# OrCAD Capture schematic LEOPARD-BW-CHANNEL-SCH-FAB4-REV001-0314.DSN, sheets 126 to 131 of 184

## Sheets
126 041_CPU2 - DDR4 (CHANNEL F): size A3; title: CPU2 - DDR4 (CHANNEL F)
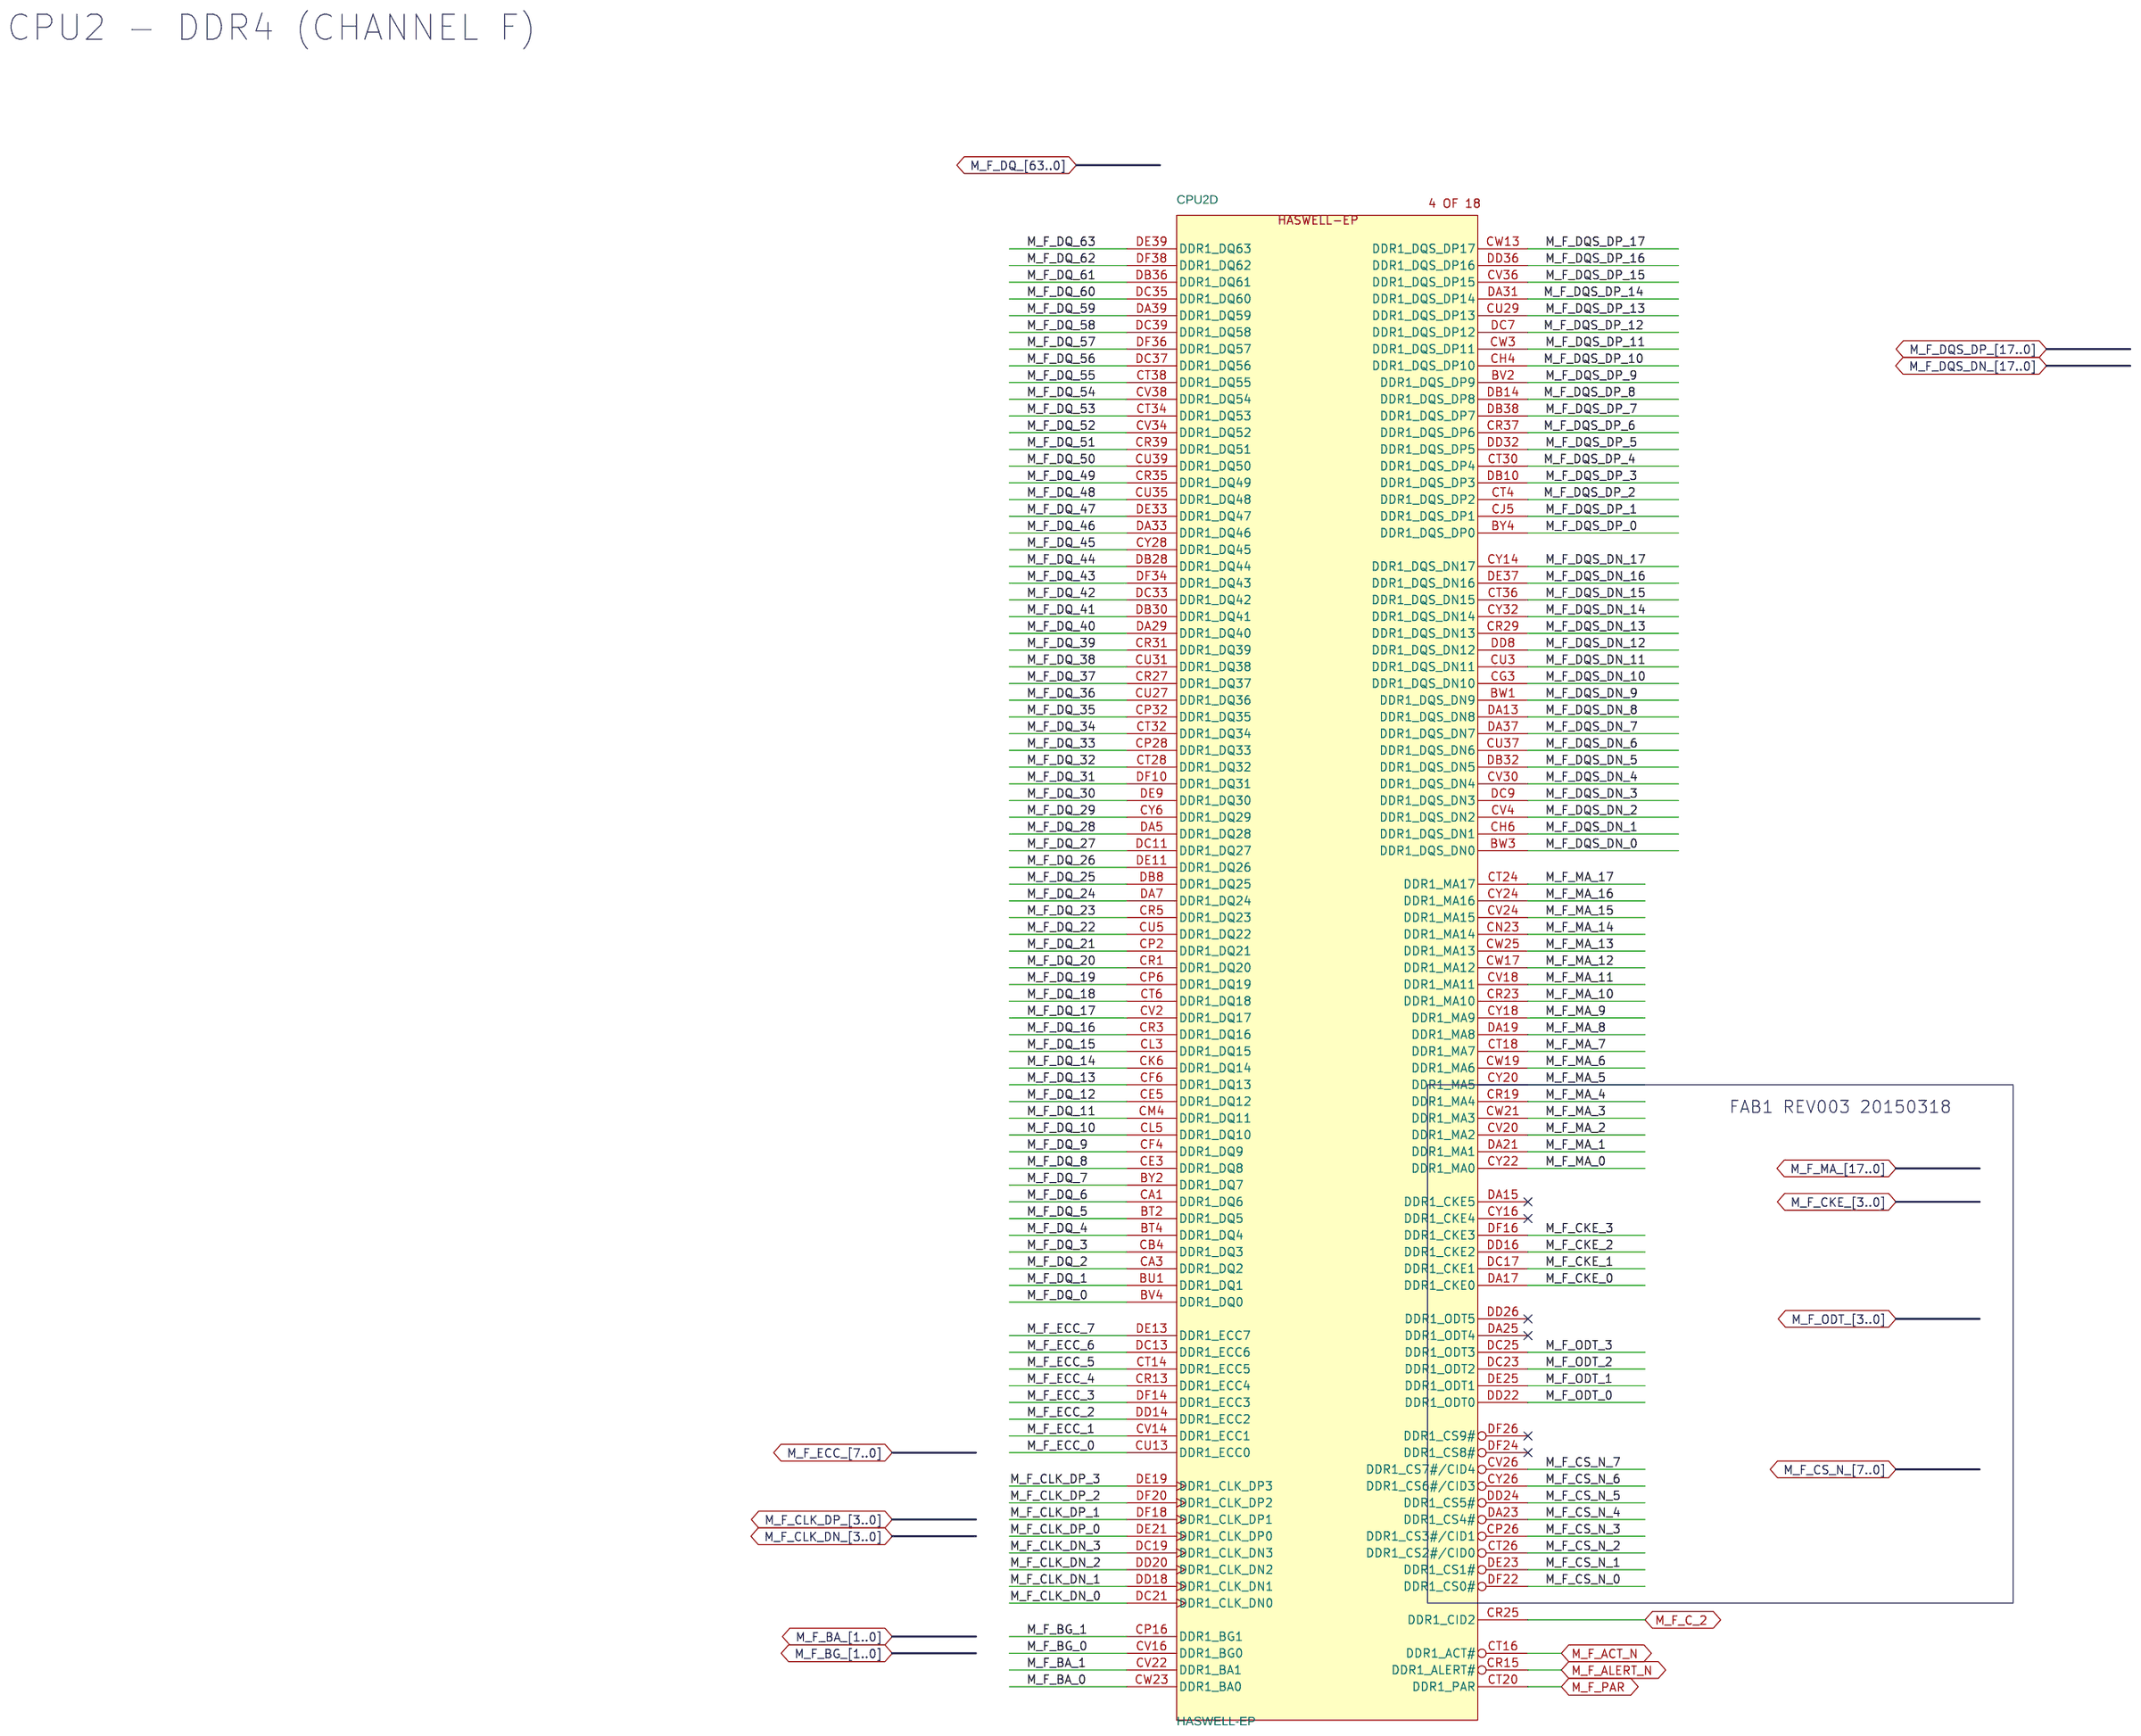
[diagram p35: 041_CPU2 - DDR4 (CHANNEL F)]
127 040_CPU2 - DDR4 (CHANNEL E): size A3; title: CPU2 - DDR4 (CHANNEL E)
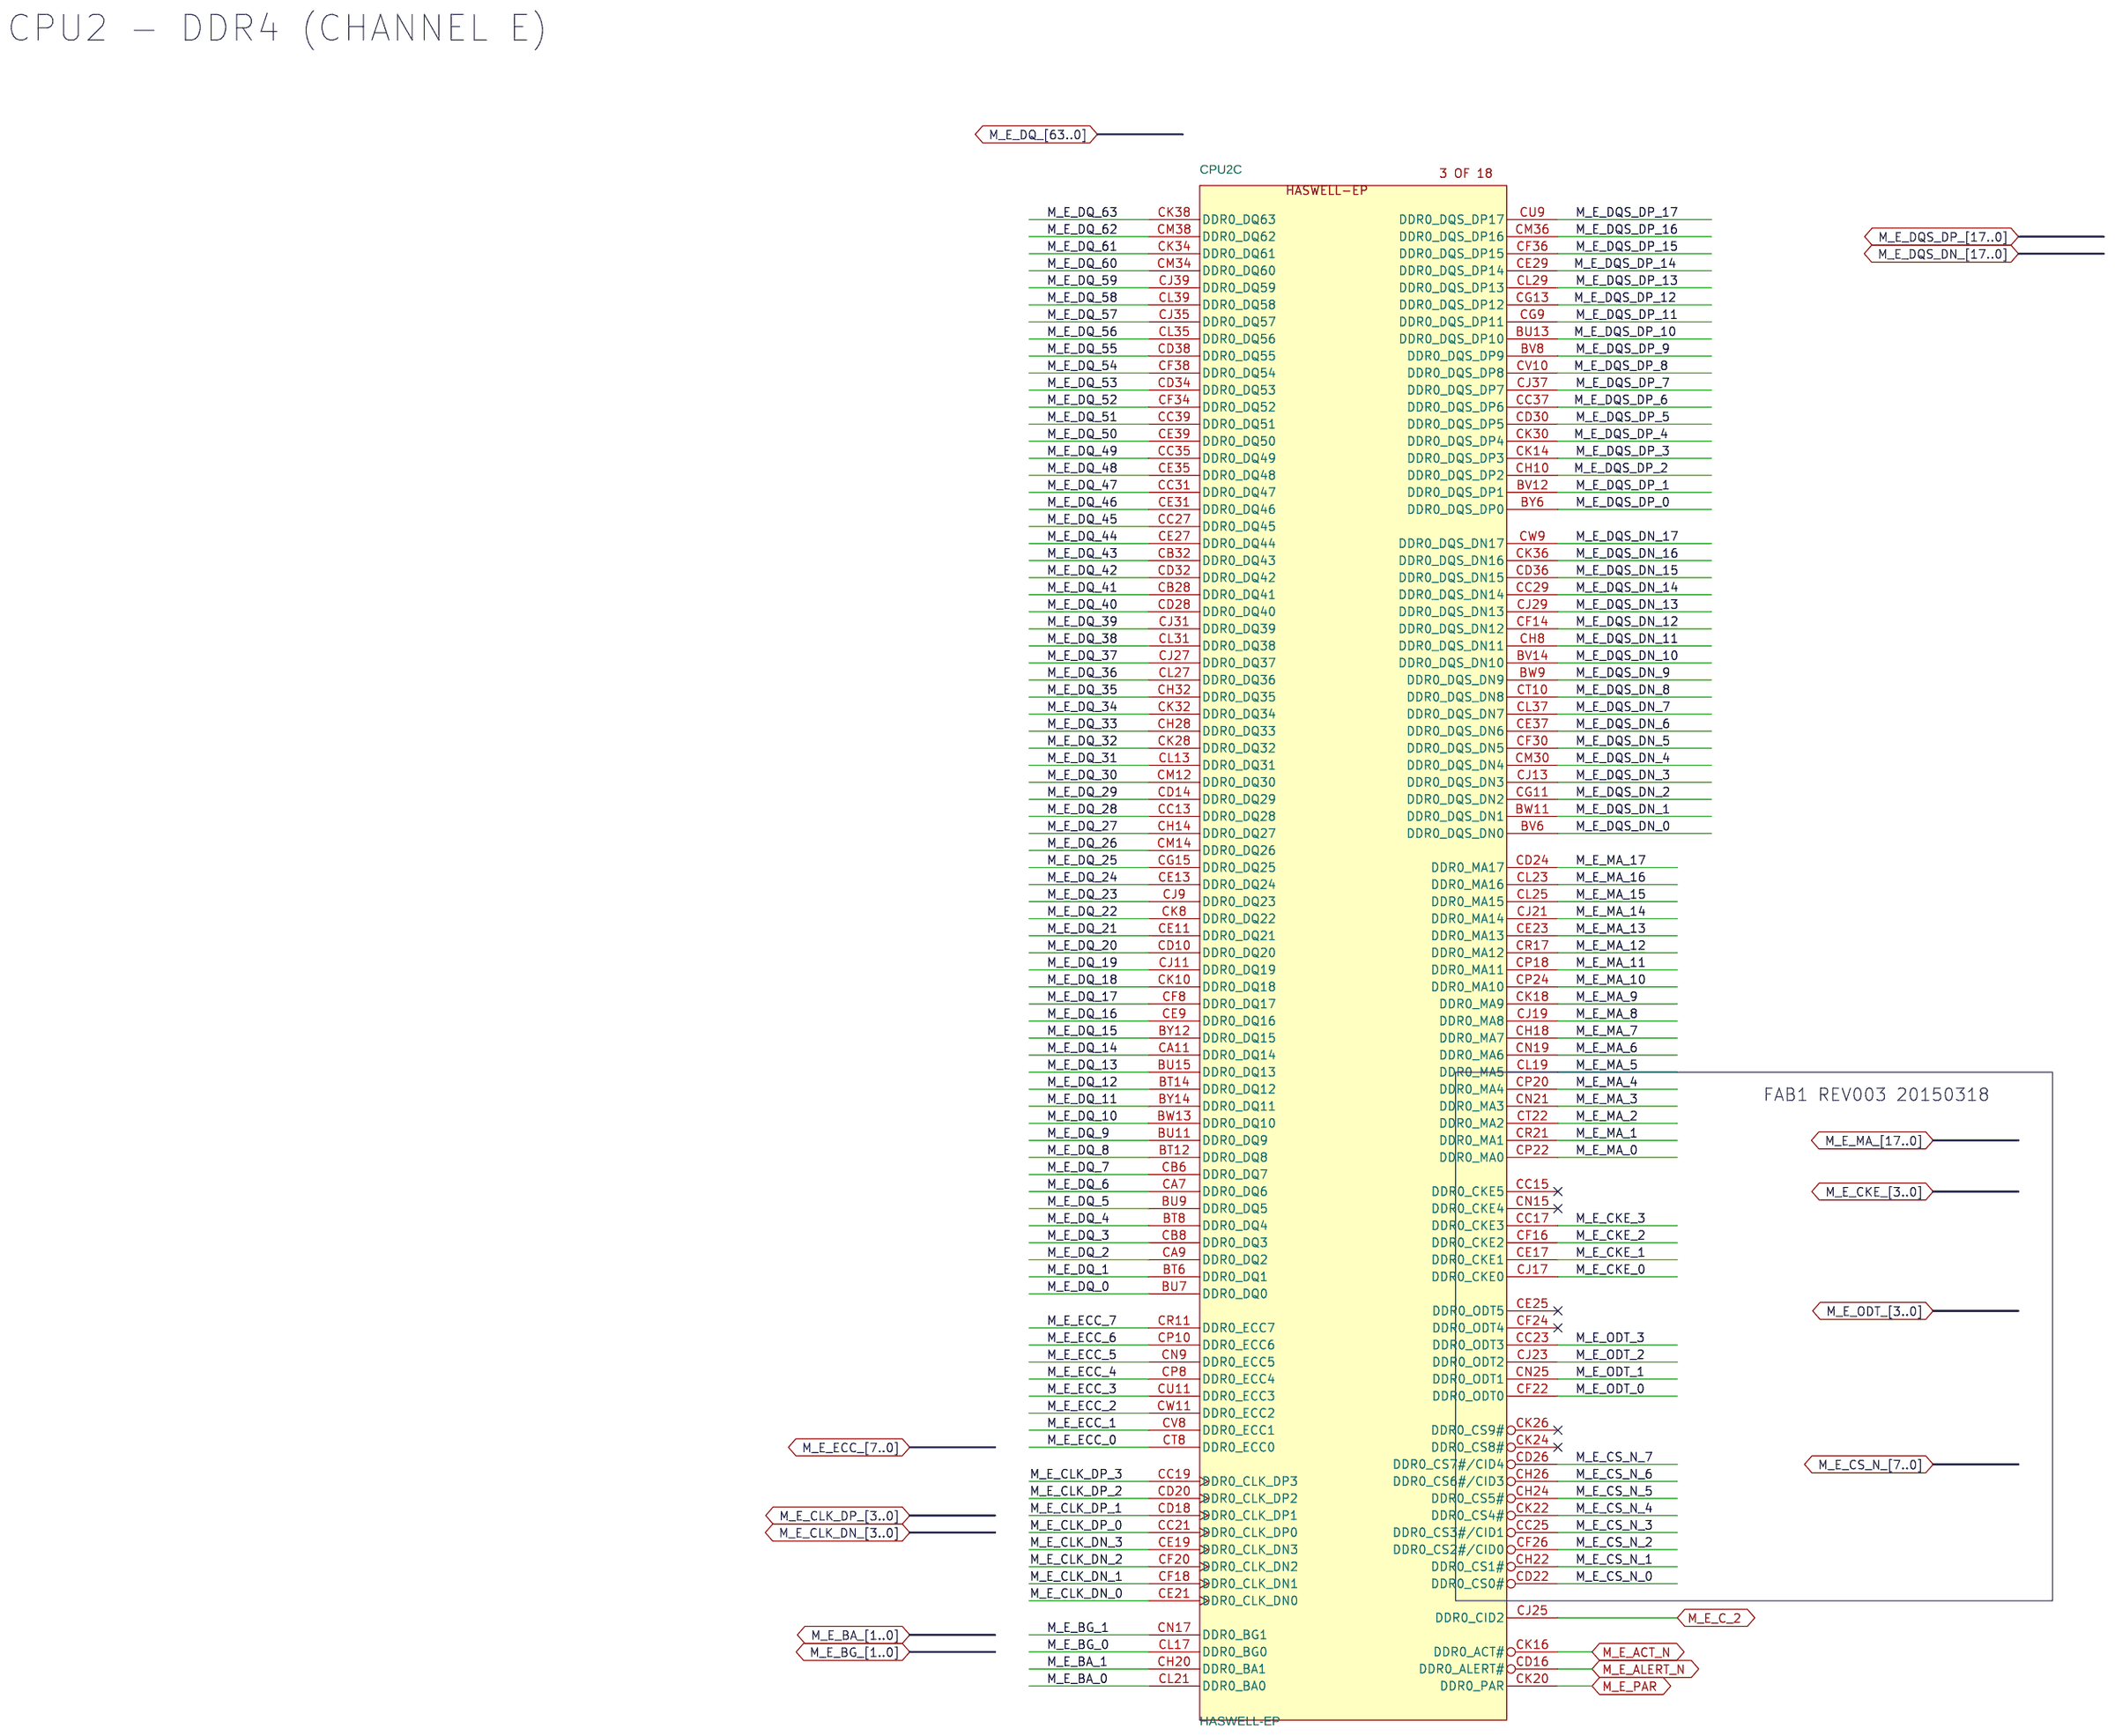
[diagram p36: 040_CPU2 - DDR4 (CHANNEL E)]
128 039_CPU2 - RESERVED PINS: size A3; title: CPU2 - RESERVED PINS
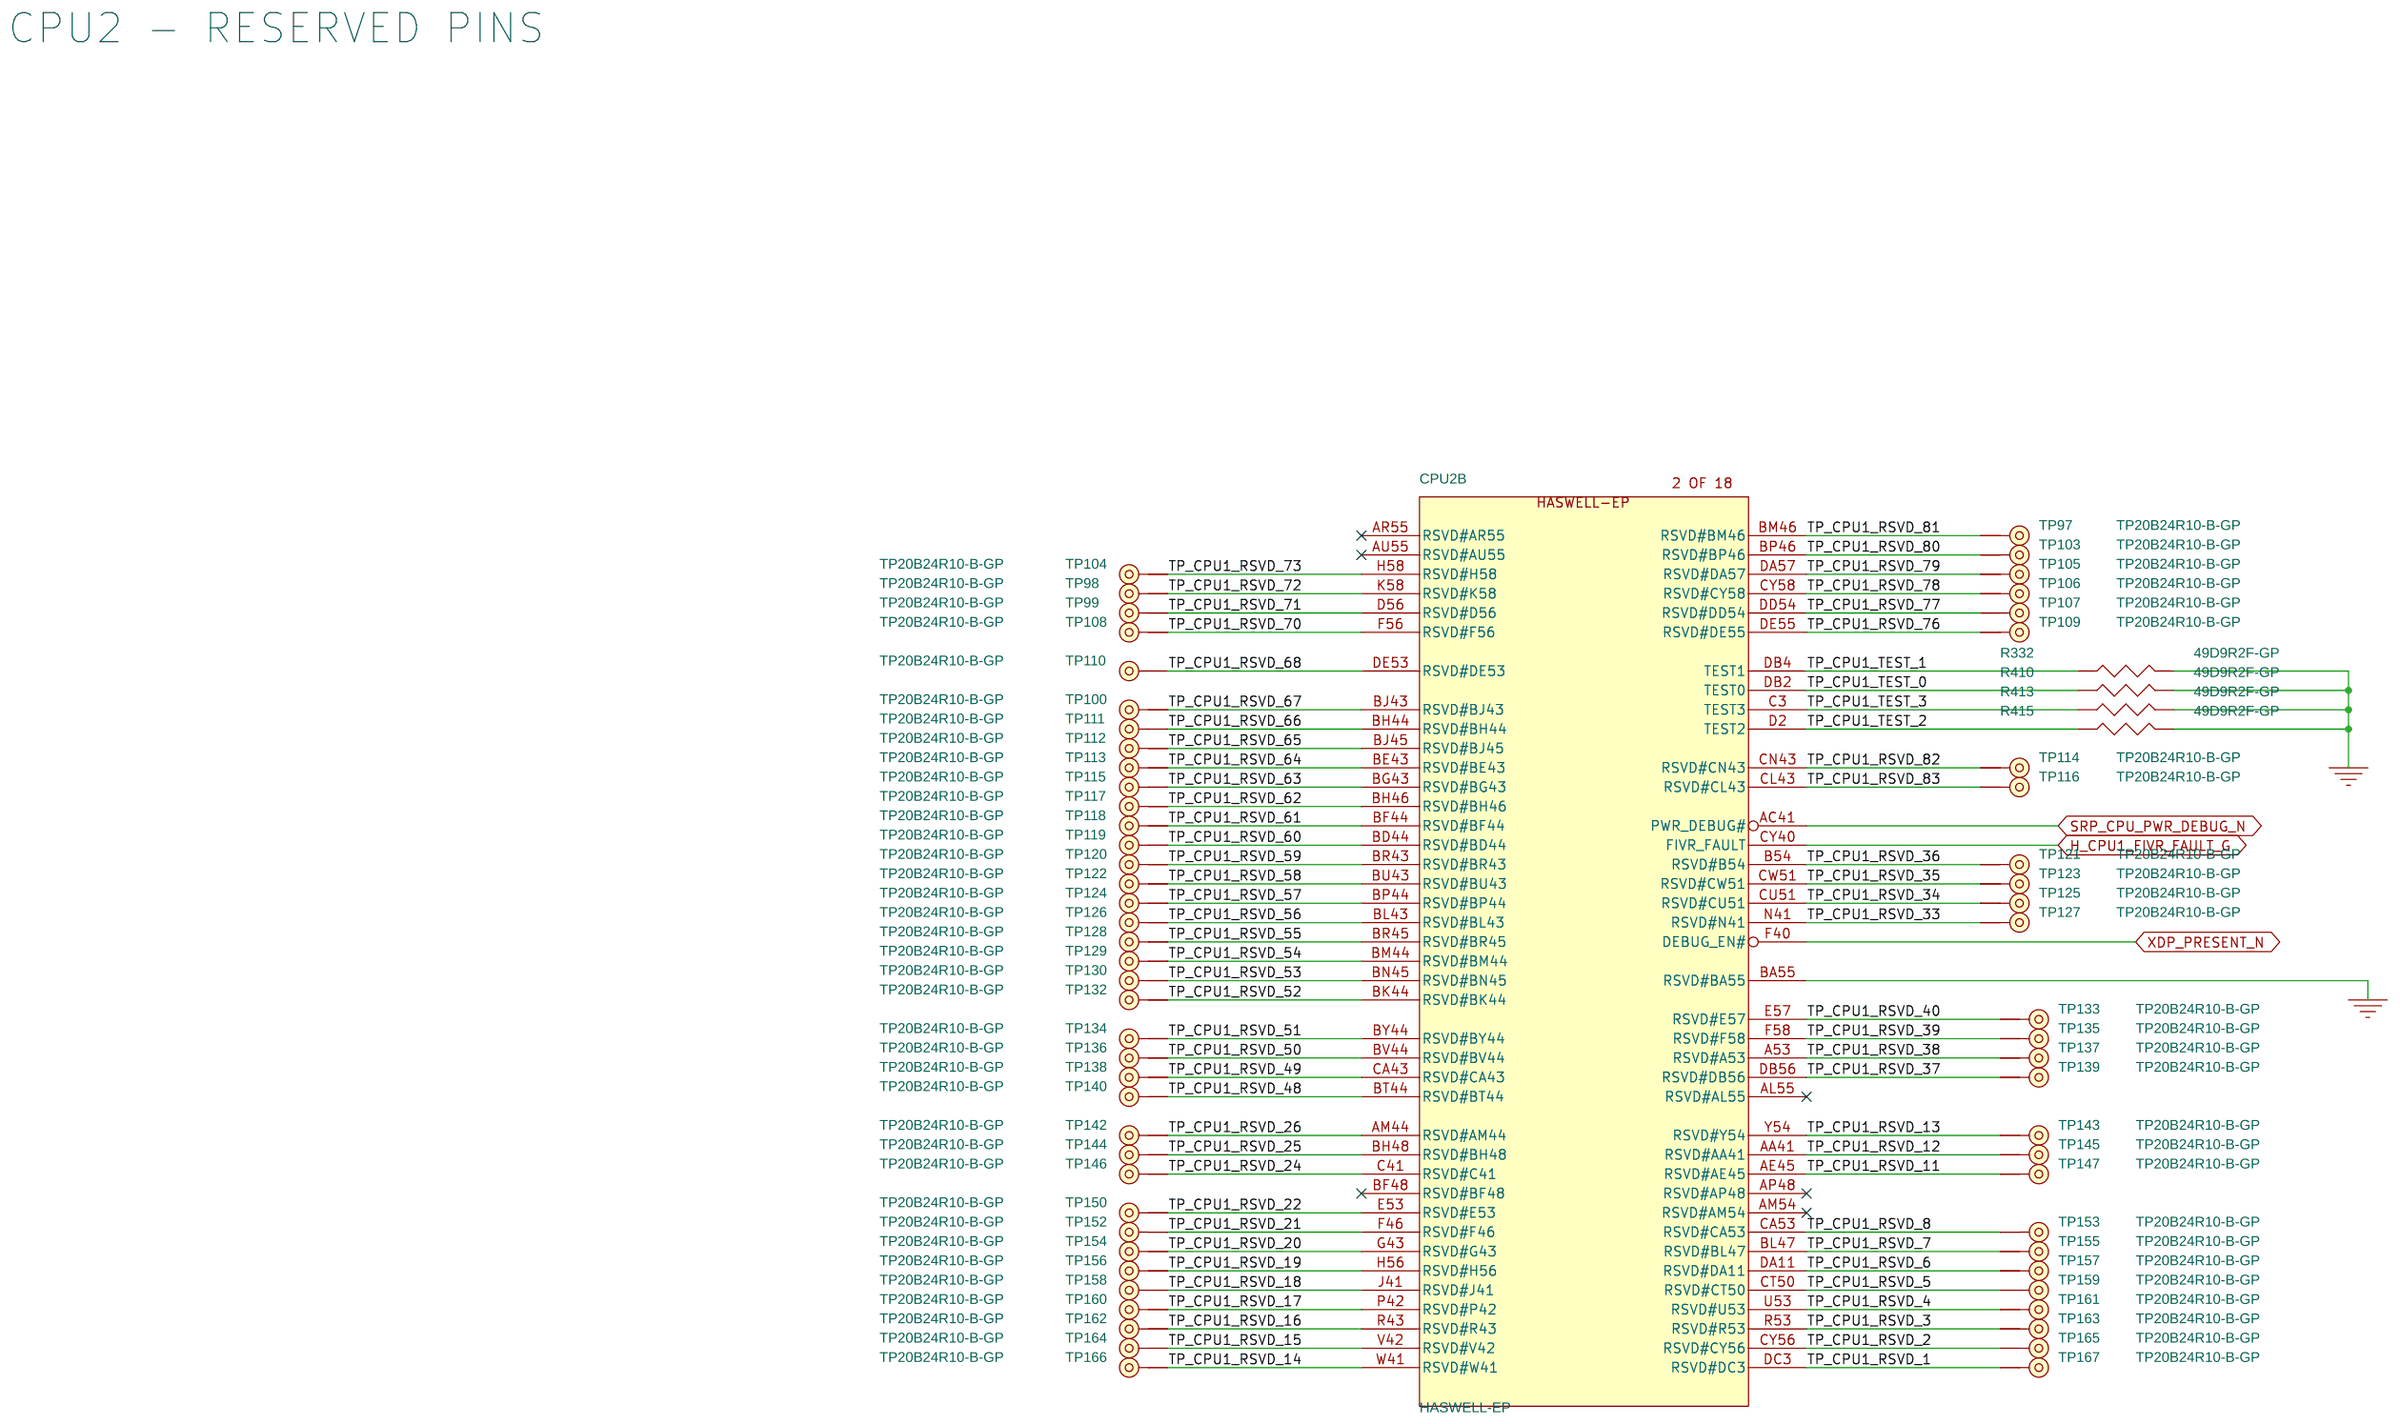
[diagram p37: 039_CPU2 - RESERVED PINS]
129 038_CPU2 - MICS: size A3; title: CPU2 - MICS
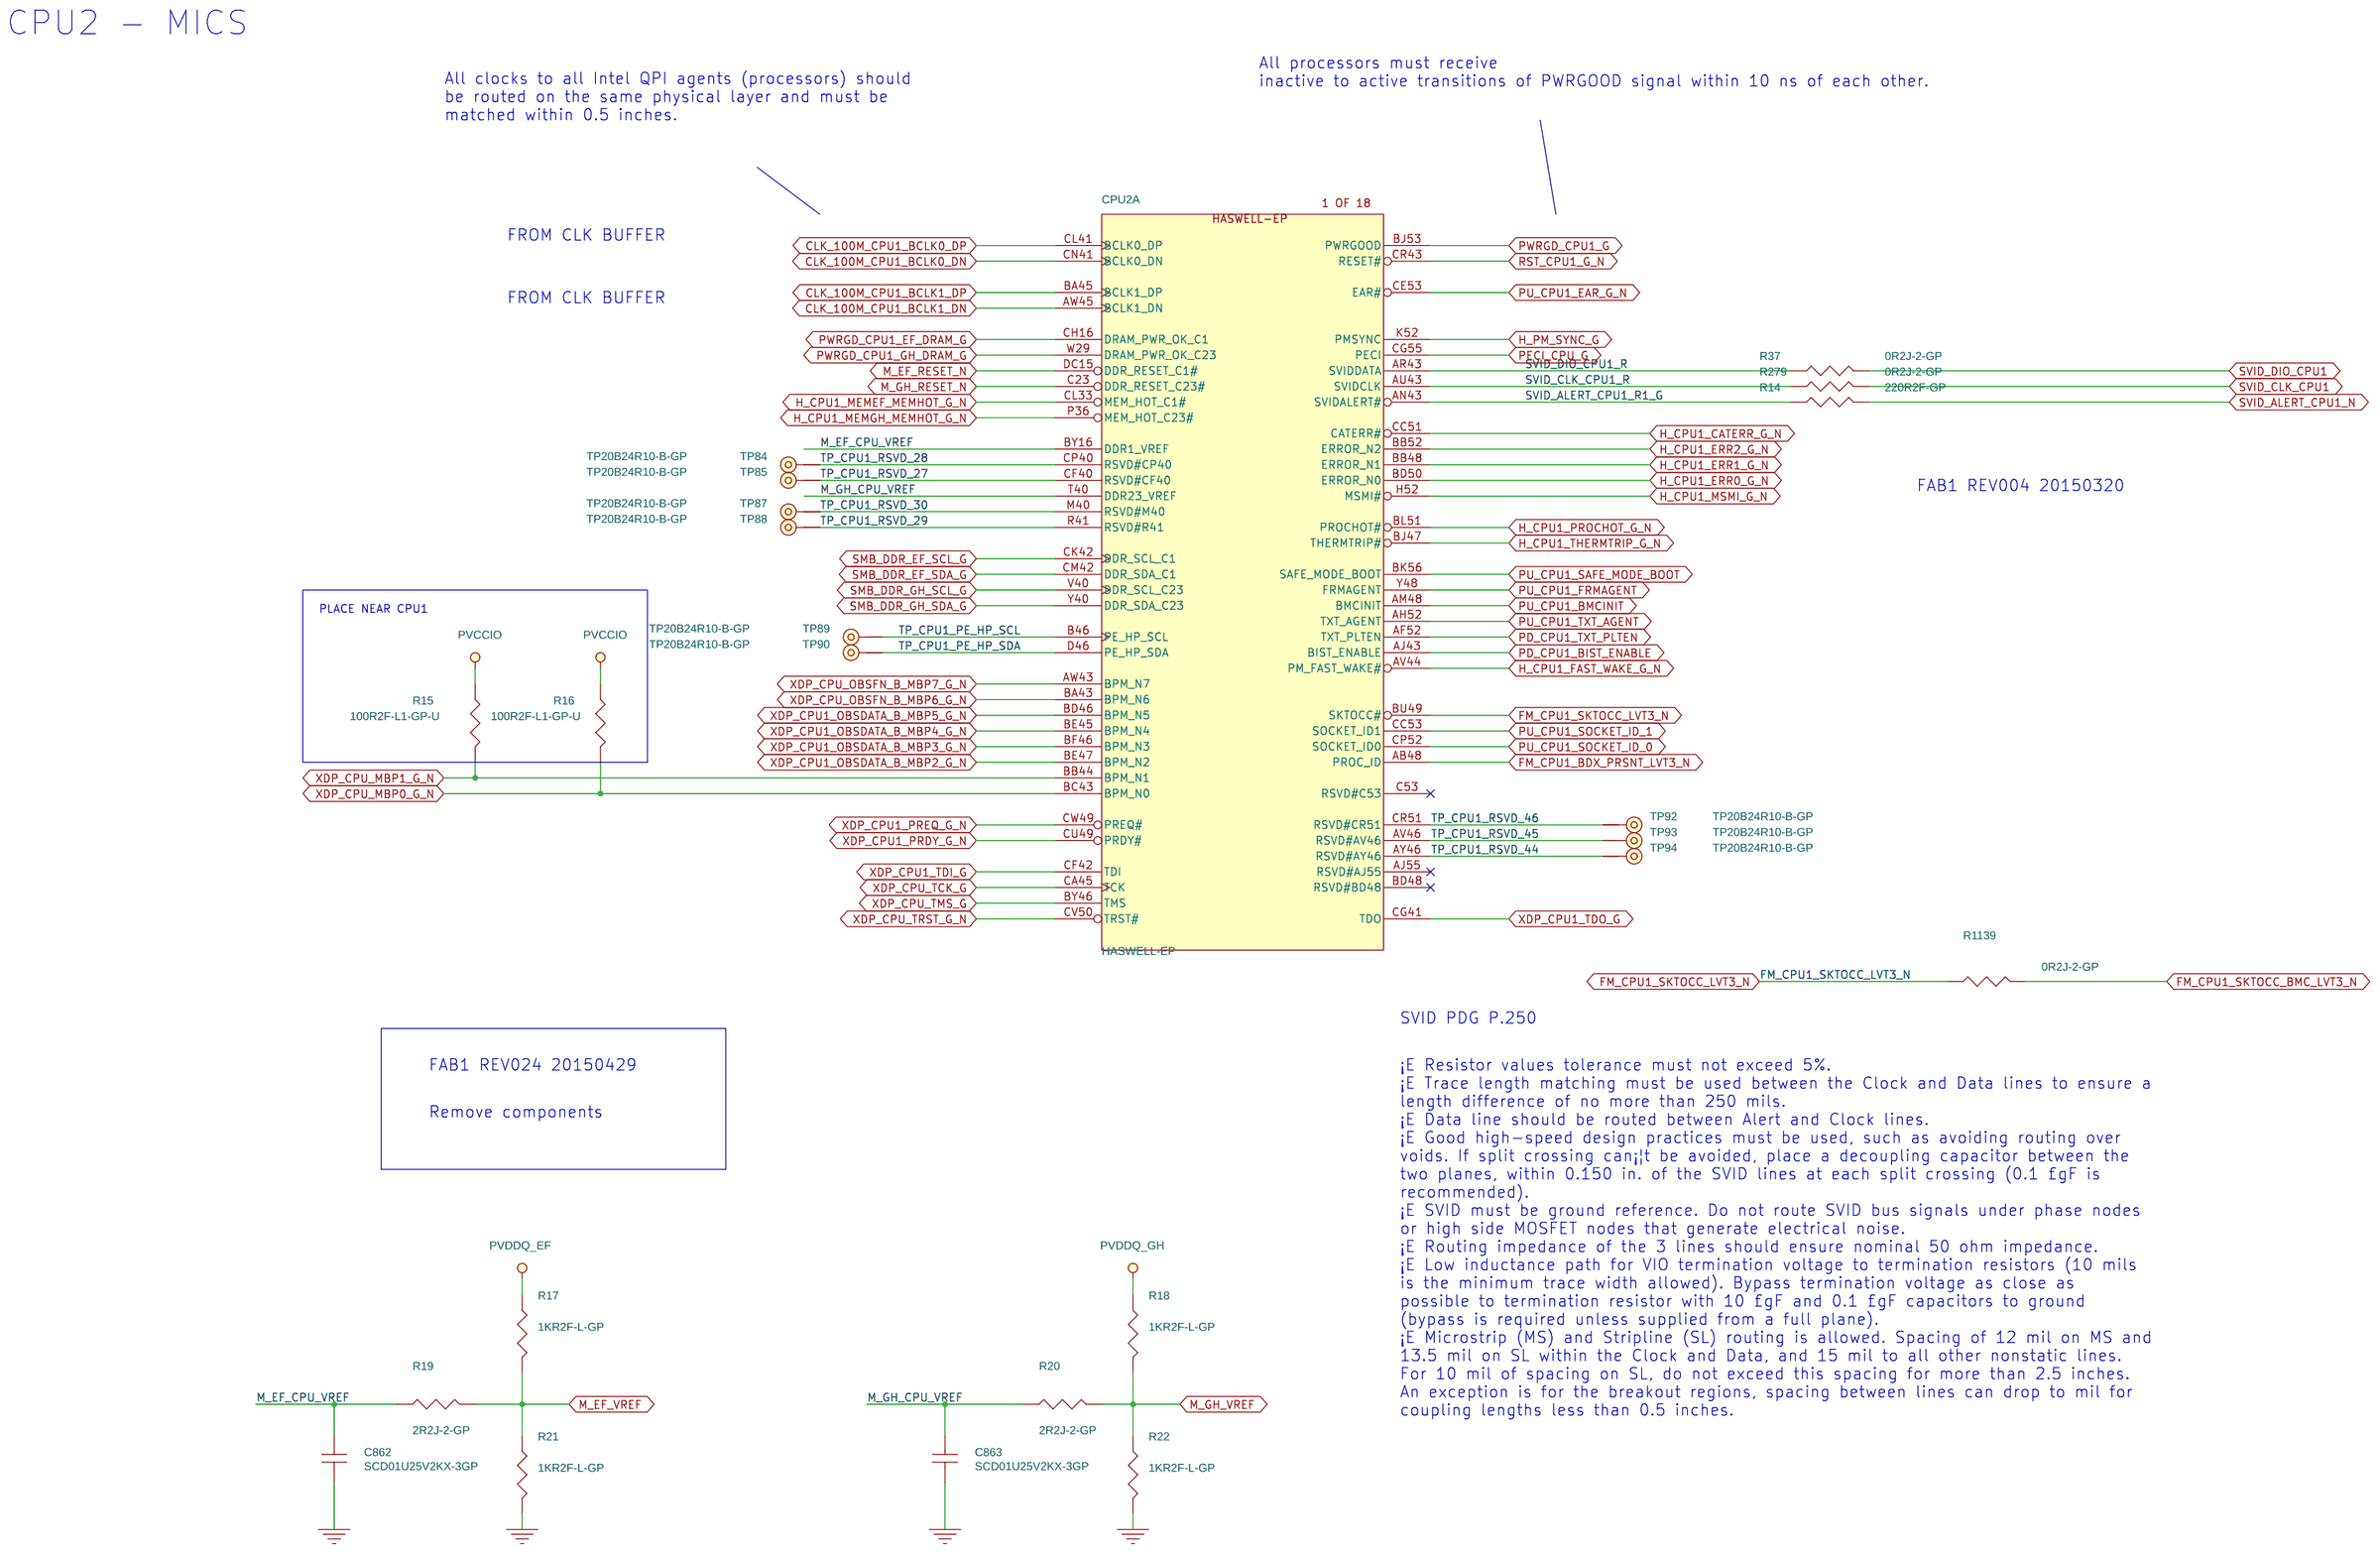
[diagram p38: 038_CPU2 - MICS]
130 035_CPU1 - VCCIN & VDDQ: size A3; title: CPU1 - VCCIN & VDDQ
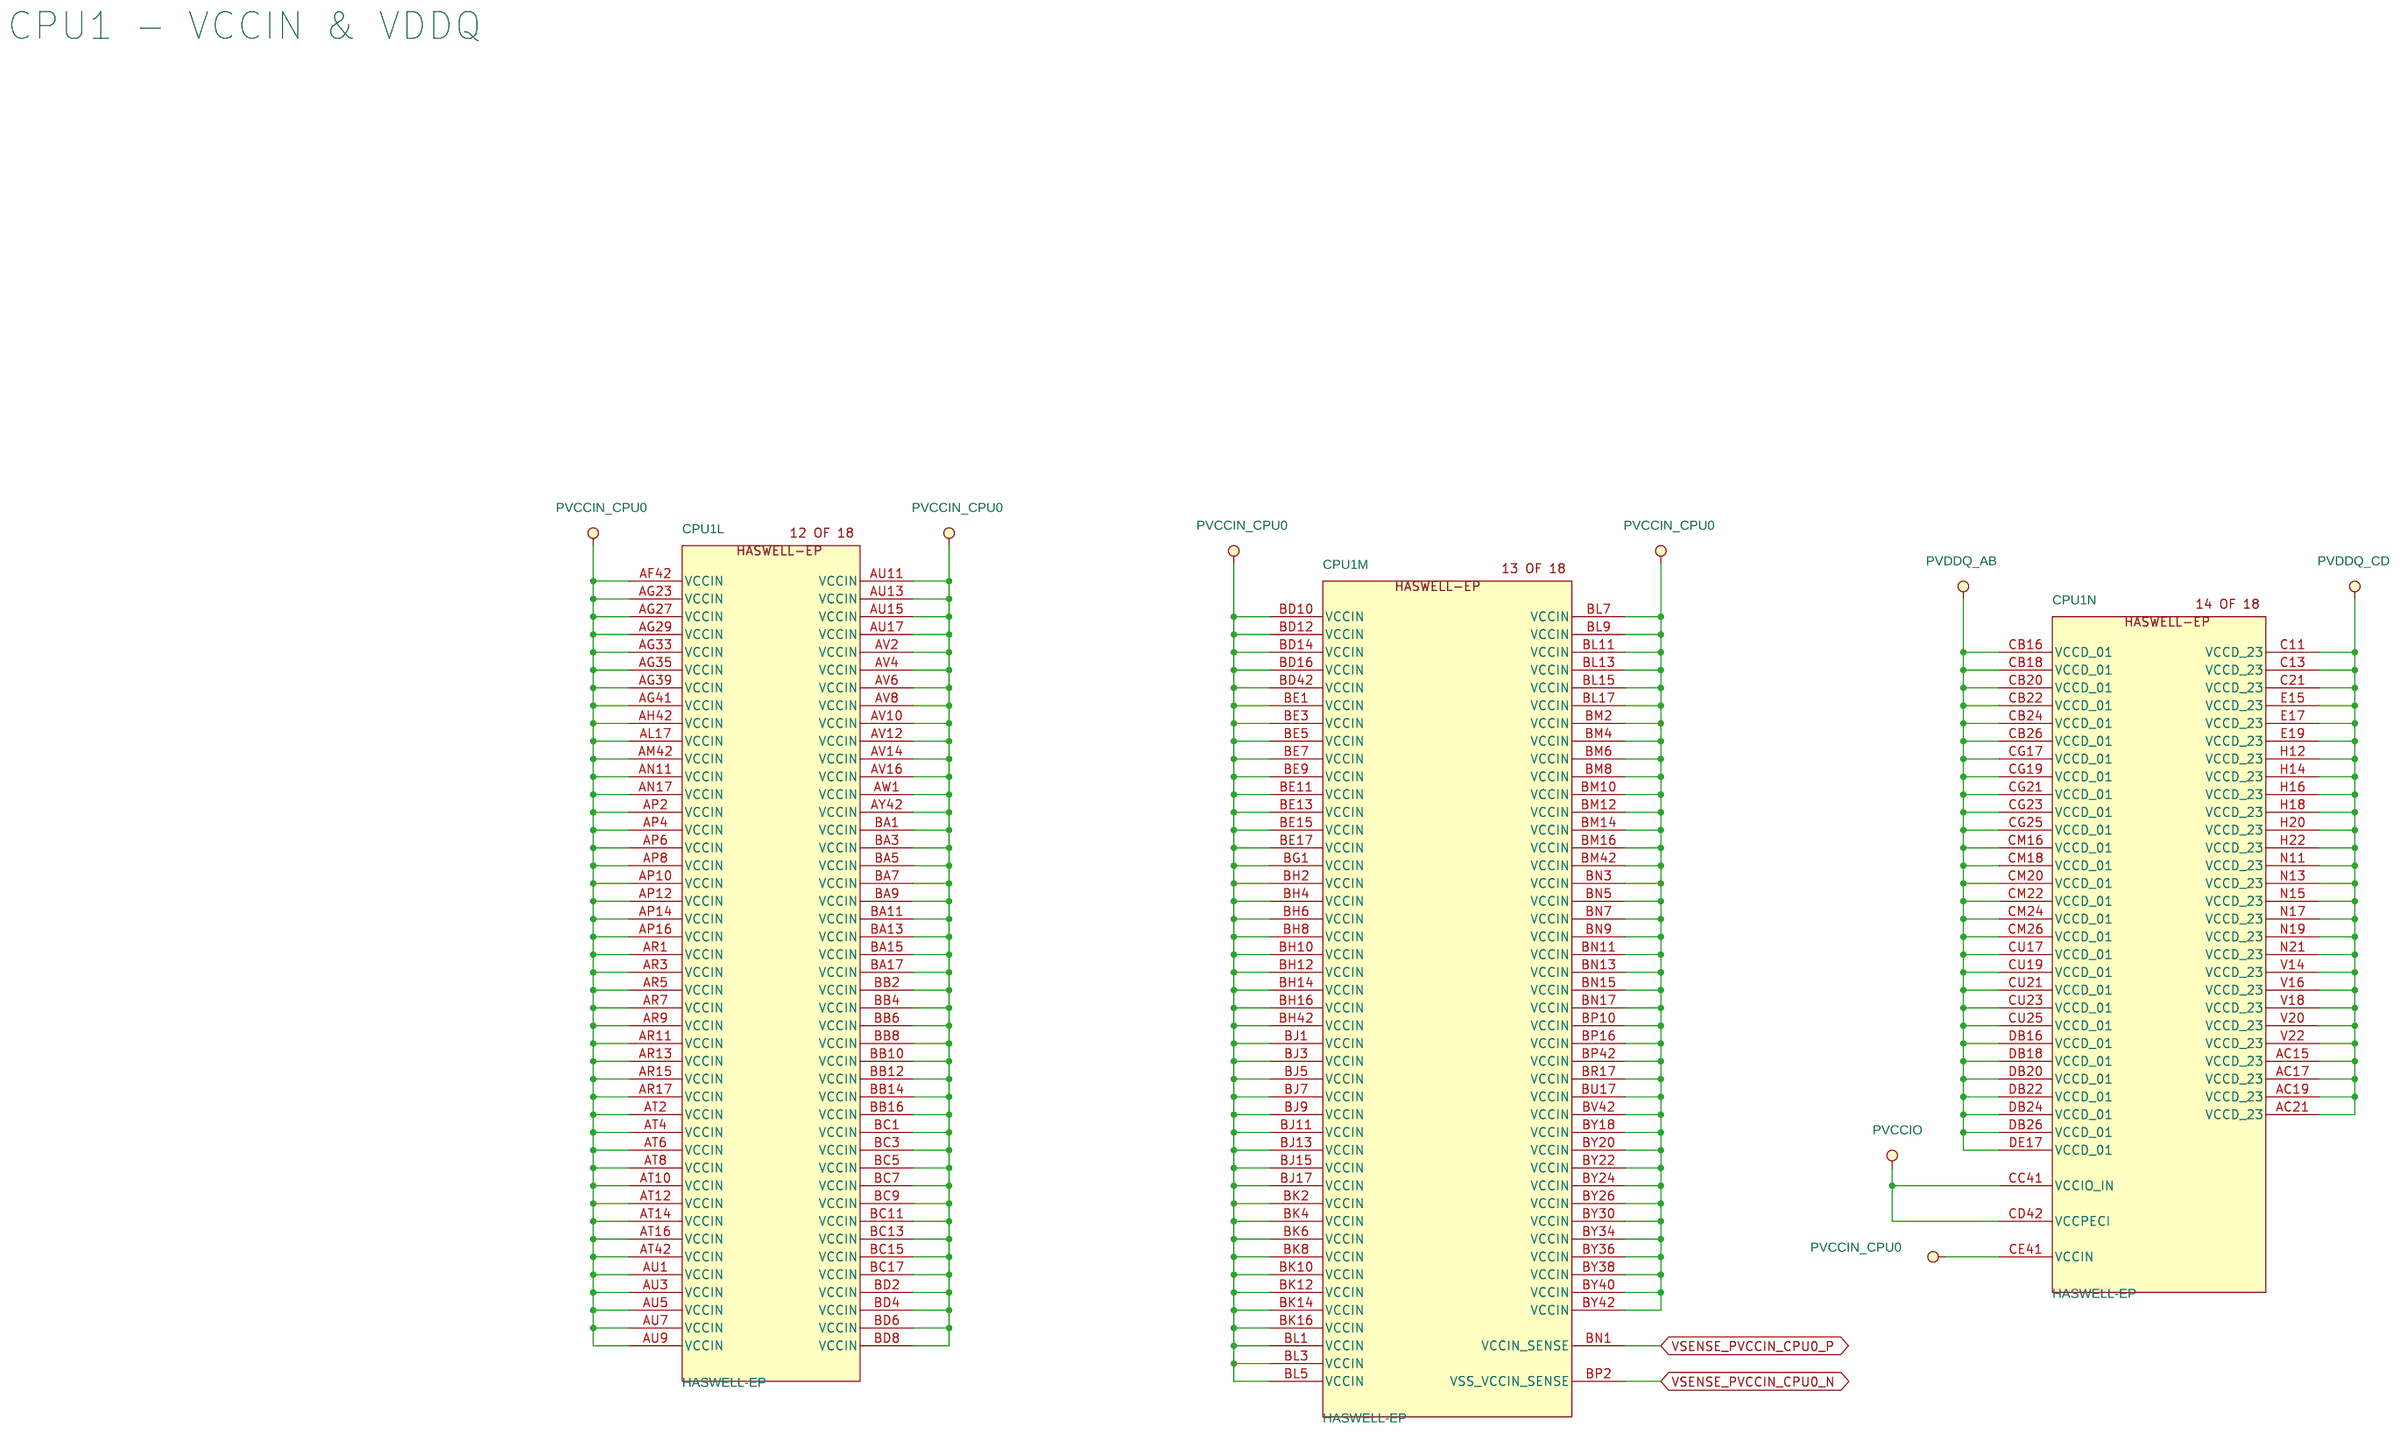
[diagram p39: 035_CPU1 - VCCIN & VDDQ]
131 032_CPU1 - PCIE (3A-3D): size A3; title: CPU1 - PCIE (3A-3D)
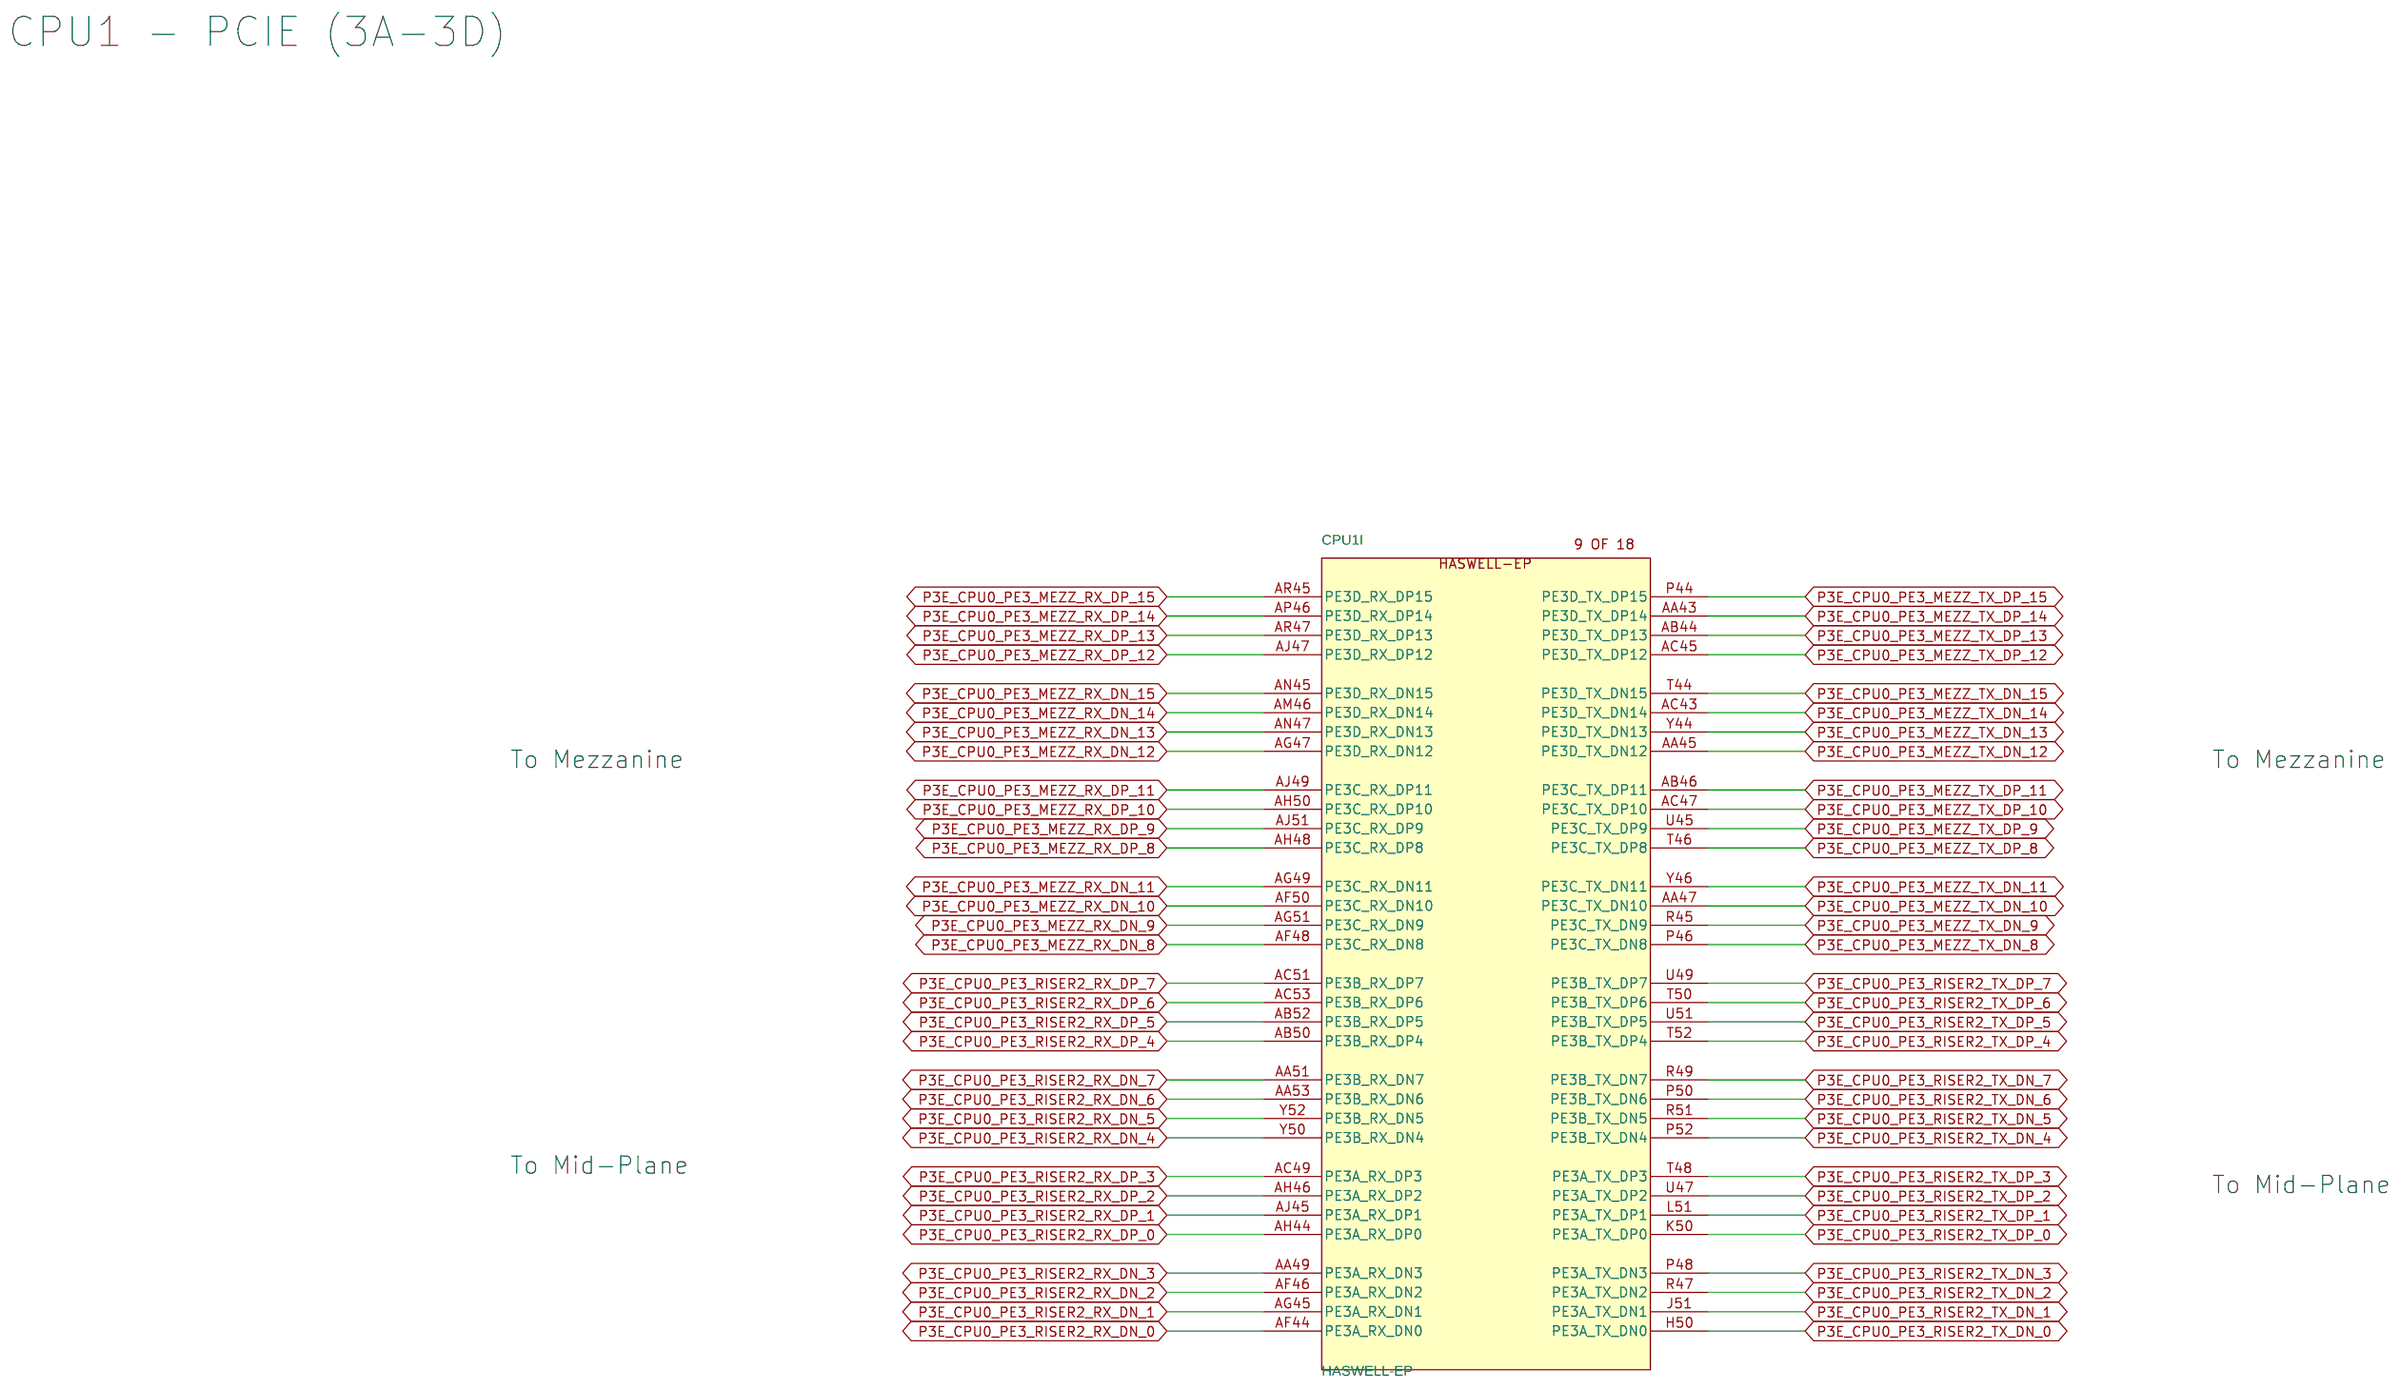
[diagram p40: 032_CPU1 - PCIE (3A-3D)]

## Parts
sheet 035_CPU1 - VCCIN & VDDQ
CPU1  HASWELL-EP  [SKT-LGA2011M6151-1H298]  (sections A,B,C,D,E,F,G,H,I,J,K,L,M,N,O,P,Q,R)
sheet 038_CPU2 - MICS
C862  SCD01U25V2KX-3GP  [C402H22]
C863  SCD01U25V2KX-3GP  [C402H22]
R14  220R2F-GP  [R402H16]
R15  100R2F-L1-GP-U  [R402H14]
R16  100R2F-L1-GP-U  [R402H14]
R17  1KR2F-L-GP  [R402H16]
R18  1KR2F-L-GP  [R402H16]
R19  2R2J-2-GP  [R402H16]
R20  2R2J-2-GP  [R402H16]
R21  1KR2F-L-GP  [R402H16]
R22  1KR2F-L-GP  [R402H16]
R37  0R2J-2-GP  [R402H16]
R279  0R2J-2-GP  [R402H16]
R1139  0R2J-2-GP  [R402H16]
TP84  TP20B24R10-B-GP  [TP20B24R10-B]
TP85  TP20B24R10-B-GP  [TP20B24R10-B]
TP87  TP20B24R10-B-GP  [TP20B24R10-B]
TP88  TP20B24R10-B-GP  [TP20B24R10-B]
TP89  TP20B24R10-B-GP  [TP20B24R10-B]
TP90  TP20B24R10-B-GP  [TP20B24R10-B]
TP92  TP20B24R10-B-GP  [TP20B24R10-B]
TP93  TP20B24R10-B-GP  [TP20B24R10-B]
TP94  TP20B24R10-B-GP  [TP20B24R10-B]
sheet 039_CPU2 - RESERVED PINS
R332  49D9R2F-GP  [R402H16]
R410  49D9R2F-GP  [R402H16]
R413  49D9R2F-GP  [R402H16]
R415  49D9R2F-GP  [R402H16]
TP97  TP20B24R10-B-GP  [TP20B24R10-B]
TP98  TP20B24R10-B-GP  [TP20B24R10-B]
TP99  TP20B24R10-B-GP  [TP20B24R10-B]
TP100  TP20B24R10-B-GP  [TP20B24R10-B]
TP103  TP20B24R10-B-GP  [TP20B24R10-B]
TP104  TP20B24R10-B-GP  [TP20B24R10-B]
TP105  TP20B24R10-B-GP  [TP20B24R10-B]
TP106  TP20B24R10-B-GP  [TP20B24R10-B]
TP107  TP20B24R10-B-GP  [TP20B24R10-B]
TP108  TP20B24R10-B-GP  [TP20B24R10-B]
TP109  TP20B24R10-B-GP  [TP20B24R10-B]
TP110  TP20B24R10-B-GP  [TP20B24R10-B]
TP111  TP20B24R10-B-GP  [TP20B24R10-B]
TP112  TP20B24R10-B-GP  [TP20B24R10-B]
TP113  TP20B24R10-B-GP  [TP20B24R10-B]
TP114  TP20B24R10-B-GP  [TP20B24R10-B]
TP115  TP20B24R10-B-GP  [TP20B24R10-B]
TP116  TP20B24R10-B-GP  [TP20B24R10-B]
TP117  TP20B24R10-B-GP  [TP20B24R10-B]
TP118  TP20B24R10-B-GP  [TP20B24R10-B]
TP119  TP20B24R10-B-GP  [TP20B24R10-B]
TP120  TP20B24R10-B-GP  [TP20B24R10-B]
TP121  TP20B24R10-B-GP  [TP20B24R10-B]
TP122  TP20B24R10-B-GP  [TP20B24R10-B]
TP123  TP20B24R10-B-GP  [TP20B24R10-B]
TP124  TP20B24R10-B-GP  [TP20B24R10-B]
TP125  TP20B24R10-B-GP  [TP20B24R10-B]
TP126  TP20B24R10-B-GP  [TP20B24R10-B]
TP127  TP20B24R10-B-GP  [TP20B24R10-B]
TP128  TP20B24R10-B-GP  [TP20B24R10-B]
TP129  TP20B24R10-B-GP  [TP20B24R10-B]
TP130  TP20B24R10-B-GP  [TP20B24R10-B]
TP132  TP20B24R10-B-GP  [TP20B24R10-B]
TP133  TP20B24R10-B-GP  [TP20B24R10-B]
TP134  TP20B24R10-B-GP  [TP20B24R10-B]
TP135  TP20B24R10-B-GP  [TP20B24R10-B]
TP136  TP20B24R10-B-GP  [TP20B24R10-B]
TP137  TP20B24R10-B-GP  [TP20B24R10-B]
TP138  TP20B24R10-B-GP  [TP20B24R10-B]
TP139  TP20B24R10-B-GP  [TP20B24R10-B]
TP140  TP20B24R10-B-GP  [TP20B24R10-B]
TP142  TP20B24R10-B-GP  [TP20B24R10-B]
TP143  TP20B24R10-B-GP  [TP20B24R10-B]
TP144  TP20B24R10-B-GP  [TP20B24R10-B]
TP145  TP20B24R10-B-GP  [TP20B24R10-B]
TP146  TP20B24R10-B-GP  [TP20B24R10-B]
TP147  TP20B24R10-B-GP  [TP20B24R10-B]
TP150  TP20B24R10-B-GP  [TP20B24R10-B]
TP152  TP20B24R10-B-GP  [TP20B24R10-B]
TP153  TP20B24R10-B-GP  [TP20B24R10-B]
TP154  TP20B24R10-B-GP  [TP20B24R10-B]
TP155  TP20B24R10-B-GP  [TP20B24R10-B]
TP156  TP20B24R10-B-GP  [TP20B24R10-B]
TP157  TP20B24R10-B-GP  [TP20B24R10-B]
TP158  TP20B24R10-B-GP  [TP20B24R10-B]
TP159  TP20B24R10-B-GP  [TP20B24R10-B]
TP160  TP20B24R10-B-GP  [TP20B24R10-B]
TP161  TP20B24R10-B-GP  [TP20B24R10-B]
TP162  TP20B24R10-B-GP  [TP20B24R10-B]
TP163  TP20B24R10-B-GP  [TP20B24R10-B]
TP164  TP20B24R10-B-GP  [TP20B24R10-B]
TP165  TP20B24R10-B-GP  [TP20B24R10-B]
TP166  TP20B24R10-B-GP  [TP20B24R10-B]
TP167  TP20B24R10-B-GP  [TP20B24R10-B]
sheet 041_CPU2 - DDR4 (CHANNEL F)
CPU2  HASWELL-EP  [SKT-LGA2011M6151-1H298]  (sections A,B,C,D,E,F,G,H,I,J,K,L,M,N,O,P,Q,R)

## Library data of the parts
CPU1 CPU2 = HASWELL-EP: SKT CPU LGA 2011P AZIF0001-P004C SMD; GREENDFACTOR: R2_C;; POP?: 62.10079.311; Package Type: SOCKET-G2; Part Number: 62.10079.261; SPEC: http://wpqssvr.wistron.com.tw:7001/wpqs/servlet/COM.qpart.Attachment?PartNumber=62.10079.261
C862 C863 = SCD01U25V2KX-3GP: CHIP 0.01U 25V K0402 X7R(ROHS); Category: CPU1; DESCRIPTIO: CHIP 0.01U 25V K0402 X7R(ROHS); GREENDFACTOR: R2_SA;HF_SA;G_SA;; Package Type: SMD-BCG; Part Number: 78.10322.2FL; Part Type: SMD-BCG; SPEC: http://wpqssvr.wistron.com.tw:7001/wpqs/servlet/COM.qpart.Attachment?PartNumber=78.10322.2FL; Type: SMD; VENDORPARTNUMBER: 04023C103KAT2A/C1005X7R103KFT/GRM155R71E103KA01D/223891715636/CL05B103KA5NNNC/TMK105BJ103KV-F/C1005X7R1E103KT000F; Vendor PN: 04023C103KAT2A/C1005X7R103KFT/GRM155R71E103KA01D/223891715636/CL05B103KA5NNNC/TMK105BJ103KV-F/C1005X7R1E103KT000F
R14 = 220R2F-GP: CHIP RES 220 F 1/16W 0402; Category: CPU0; GREENDFACTOR: R2_SA;HF_SA;G_SA;; Package Type: RCL_GP; Part Number: 64.22005.6DL; SPEC: http://wpqssvr.wistron.com.tw:7001/wpqs/servlet/COM.qpart.Attachment?PartNumber=64.22005.6DL
R15 R16 = 100R2F-L1-GP-U: CHIP RES 100 F 1/16W 0402; Category: CPU1; Part Number: 64.10005.6DL; Part Type: SMD-RG
R17 R18 R21 R22 = 1KR2F-L-GP: CHIP RES 1K F 1/16W 0402; Category: CPU1; Part Number: 64.10015.L1L; Part Type: SMD-RG2
R19 R20 = 2R2J-2-GP: CHIP RES 2 J 1/16W 0402; Category: CPU1; GREENDFACTOR: R2_SA;HF_SA;G_SA;; Package Type: SMD-RG1; Part Number: 63.2R034.1DL; SPEC: http://wpqssvr.wistron.com.tw:7001/wpqs/servlet/COM.qpart.Attachment?PartNumber=63.2R034.1DL
R37 R279 R1139 = 0R2J-2-GP: CHIP RES 0 J 1/16W 0402; Category: BMC; DESCRIPTIO: CHIP RES 0 J 1/16W 0402; GREENDFACTOR: R2_SA;HF_SA;G_SA;; Package Type: SMD-RG; Part Number: 63.R0034.1DL; Part Type: SMD-RG; SPEC: http://wpqssvr.wistron.com.tw:7001/wpqs/servlet/COM.qpart.Attachment?PartNumber=63.R0034.1DL; VENDORPARTNUMBER: RM04JTN0/RTT02000JTH/RR0510X-000-XN/RC0402JR-070RL/WR04X000 PTL
TP84 TP85 TP87-TP90 TP92-TP94 TP97-TP100 TP103-TP130 TP132-TP140 TP142-TP147 TP150 TP152-TP167 = TP20B24R10-B-GP_4: TEST VIA FOR DRILL 10MIL; GREENDFACTOR: R2_C;; Package Type: DISCRET-G5; Part Number: ZZ.0TPAD.211; SPEC: http://wpqssvr.wistron.com.tw:7001/wpqs/servlet/COM.qpart.Attachment?PartNumber=ZZ.0TPAD.211
R332 R410 R413 R415 = 49D9R2F-GP: CHIP RES 49.9 F 1/16W 0402; Category: CPU1; Part Number: 64.49R95.6DL; Part Type: RCL_GP

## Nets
GND: C862.2 C863.2 CPU2.BA55(RSVD#BA55) R21.2 R22.2 R332.2 R410.2 R413.2 R415.2 ; also on sheet 1 2 3 4 5 6 7 8 9 10 11 12 13 14 15 16 17 18 19 20 21 22 23 24 25 26 27 28 29 30 31 32 33 34 35 36 37 38 39 44 46 47 49 50 51 52 53 54 55 56 57 58 59 60 61 62 63 64 65 66 69 70 71 73 74 75 76 78 79 80 81 82 83 84 86 87 88 89 90 91 92 93 94 95 96 97 98 99 100 101 102 103 104 105 106 107 108 109 110 111 112 113 114 115 116 117 118 119 138 139 159 160 161 166 168 169 170 171 172 173 174 175 176 177 180 181 182 183 184
PVCCIN_CPU0: CPU1.AF42(VCCIN) CPU1.AG23(VCCIN) CPU1.AG27(VCCIN) CPU1.AG29(VCCIN) CPU1.AG33(VCCIN) CPU1.AG35(VCCIN) CPU1.AG39(VCCIN) CPU1.AG41(VCCIN) CPU1.AH42(VCCIN) CPU1.AL17(VCCIN) CPU1.AM42(VCCIN) CPU1.AN11(VCCIN) CPU1.AN17(VCCIN) CPU1.AP2(VCCIN) CPU1.AP4(VCCIN) CPU1.AP6(VCCIN) CPU1.AP8(VCCIN) CPU1.AP10(VCCIN) CPU1.AP12(VCCIN) CPU1.AP14(VCCIN) CPU1.AP16(VCCIN) CPU1.AR1(VCCIN) CPU1.AR3(VCCIN) CPU1.AR5(VCCIN) CPU1.AR7(VCCIN) CPU1.AR9(VCCIN) CPU1.AR11(VCCIN) CPU1.AR13(VCCIN) CPU1.AR15(VCCIN) CPU1.AR17(VCCIN) CPU1.AT2(VCCIN) CPU1.AT4(VCCIN) CPU1.AT6(VCCIN) CPU1.AT8(VCCIN) CPU1.AT10(VCCIN) CPU1.AT12(VCCIN) CPU1.AT14(VCCIN) CPU1.AT16(VCCIN) CPU1.AT42(VCCIN) CPU1.AU1(VCCIN) CPU1.AU3(VCCIN) CPU1.AU5(VCCIN) CPU1.AU7(VCCIN) CPU1.AU9(VCCIN) CPU1.AU11(VCCIN) CPU1.AU13(VCCIN) CPU1.AU15(VCCIN) CPU1.AU17(VCCIN) CPU1.AV2(VCCIN) CPU1.AV4(VCCIN) CPU1.AV6(VCCIN) CPU1.AV8(VCCIN) CPU1.AV10(VCCIN) CPU1.AV12(VCCIN) CPU1.AV14(VCCIN) CPU1.AV16(VCCIN) CPU1.AW1(VCCIN) CPU1.AY42(VCCIN) CPU1.BA1(VCCIN) CPU1.BA3(VCCIN) CPU1.BA5(VCCIN) CPU1.BA7(VCCIN) CPU1.BA9(VCCIN) CPU1.BA11(VCCIN) CPU1.BA13(VCCIN) CPU1.BA15(VCCIN) CPU1.BA17(VCCIN) CPU1.BB2(VCCIN) CPU1.BB4(VCCIN) CPU1.BB6(VCCIN) CPU1.BB8(VCCIN) CPU1.BB10(VCCIN) CPU1.BB12(VCCIN) CPU1.BB14(VCCIN) CPU1.BB16(VCCIN) CPU1.BC1(VCCIN) CPU1.BC3(VCCIN) CPU1.BC5(VCCIN) CPU1.BC7(VCCIN) CPU1.BC9(VCCIN) CPU1.BC11(VCCIN) CPU1.BC13(VCCIN) CPU1.BC15(VCCIN) CPU1.BC17(VCCIN) CPU1.BD2(VCCIN) CPU1.BD4(VCCIN) CPU1.BD6(VCCIN) CPU1.BD8(VCCIN) CPU1.BD10(VCCIN) CPU1.BD12(VCCIN) CPU1.BD14(VCCIN) CPU1.BD16(VCCIN) CPU1.BD42(VCCIN) CPU1.BE1(VCCIN) CPU1.BE3(VCCIN) CPU1.BE5(VCCIN) CPU1.BE7(VCCIN) CPU1.BE9(VCCIN) CPU1.BE11(VCCIN) CPU1.BE13(VCCIN) CPU1.BE15(VCCIN) CPU1.BE17(VCCIN) CPU1.BG1(VCCIN) CPU1.BH2(VCCIN) CPU1.BH4(VCCIN) CPU1.BH6(VCCIN) CPU1.BH8(VCCIN) CPU1.BH10(VCCIN) CPU1.BH12(VCCIN) CPU1.BH14(VCCIN) CPU1.BH16(VCCIN) CPU1.BH42(VCCIN) CPU1.BJ1(VCCIN) CPU1.BJ3(VCCIN) CPU1.BJ5(VCCIN) CPU1.BJ7(VCCIN) CPU1.BJ9(VCCIN) CPU1.BJ11(VCCIN) CPU1.BJ13(VCCIN) CPU1.BJ15(VCCIN) CPU1.BJ17(VCCIN) CPU1.BK2(VCCIN) CPU1.BK4(VCCIN) CPU1.BK6(VCCIN) CPU1.BK8(VCCIN) CPU1.BK10(VCCIN) CPU1.BK12(VCCIN) CPU1.BK14(VCCIN) CPU1.BK16(VCCIN) CPU1.BL1(VCCIN) CPU1.BL3(VCCIN) CPU1.BL5(VCCIN) CPU1.BL7(VCCIN) CPU1.BL9(VCCIN) CPU1.BL11(VCCIN) CPU1.BL13(VCCIN) CPU1.BL15(VCCIN) CPU1.BL17(VCCIN) CPU1.BM2(VCCIN) CPU1.BM4(VCCIN) CPU1.BM6(VCCIN) CPU1.BM8(VCCIN) CPU1.BM10(VCCIN) CPU1.BM12(VCCIN) CPU1.BM14(VCCIN) CPU1.BM16(VCCIN) CPU1.BM42(VCCIN) CPU1.BN3(VCCIN) CPU1.BN5(VCCIN) CPU1.BN7(VCCIN) CPU1.BN9(VCCIN) CPU1.BN11(VCCIN) CPU1.BN13(VCCIN) CPU1.BN15(VCCIN) CPU1.BN17(VCCIN) CPU1.BP10(VCCIN) CPU1.BP16(VCCIN) CPU1.BP42(VCCIN) CPU1.BR17(VCCIN) CPU1.BU17(VCCIN) CPU1.BV42(VCCIN) CPU1.BY18(VCCIN) CPU1.BY20(VCCIN) CPU1.BY22(VCCIN) CPU1.BY24(VCCIN) CPU1.BY26(VCCIN) CPU1.BY30(VCCIN) CPU1.BY34(VCCIN) CPU1.BY36(VCCIN) CPU1.BY38(VCCIN) CPU1.BY40(VCCIN) CPU1.BY42(VCCIN) CPU1.CE41(VCCIN) ; also on sheet 36 37 38
PVCCIO: CPU1.CC41(VCCIO_IN) CPU1.CD42(VCCPECI) R15.1 R16.1 ; also on sheet 11 16 26 35 39 46 47 68 87 97 100 101 102 103 120 139 160 173 177 179 182
PVDDQ_AB: CPU1.CB16(VCCD_01) CPU1.CB18(VCCD_01) CPU1.CB20(VCCD_01) CPU1.CB22(VCCD_01) CPU1.CB24(VCCD_01) CPU1.CB26(VCCD_01) CPU1.CG17(VCCD_01) CPU1.CG19(VCCD_01) CPU1.CG21(VCCD_01) CPU1.CG23(VCCD_01) CPU1.CG25(VCCD_01) CPU1.CM16(VCCD_01) CPU1.CM18(VCCD_01) CPU1.CM20(VCCD_01) CPU1.CM22(VCCD_01) CPU1.CM24(VCCD_01) CPU1.CM26(VCCD_01) CPU1.CU17(VCCD_01) CPU1.CU19(VCCD_01) CPU1.CU21(VCCD_01) CPU1.CU23(VCCD_01) CPU1.CU25(VCCD_01) CPU1.DB16(VCCD_01) CPU1.DB18(VCCD_01) CPU1.DB20(VCCD_01) CPU1.DB22(VCCD_01) CPU1.DB24(VCCD_01) CPU1.DB26(VCCD_01) CPU1.DE17(VCCD_01) ; also on sheet 28 30 45 52 97 116 117 118 119 139
PVDDQ_CD: CPU1.AC15(VCCD_23) CPU1.AC17(VCCD_23) CPU1.AC19(VCCD_23) CPU1.AC21(VCCD_23) CPU1.C11(VCCD_23) CPU1.C13(VCCD_23) CPU1.C21(VCCD_23) CPU1.E15(VCCD_23) CPU1.E17(VCCD_23) CPU1.E19(VCCD_23) CPU1.H12(VCCD_23) CPU1.H14(VCCD_23) CPU1.H16(VCCD_23) CPU1.H18(VCCD_23) CPU1.H20(VCCD_23) CPU1.H22(VCCD_23) CPU1.N11(VCCD_23) CPU1.N13(VCCD_23) CPU1.N15(VCCD_23) CPU1.N17(VCCD_23) CPU1.N19(VCCD_23) CPU1.N21(VCCD_23) CPU1.V14(VCCD_23) CPU1.V16(VCCD_23) CPU1.V18(VCCD_23) CPU1.V20(VCCD_23) CPU1.V22(VCCD_23) ; also on sheet 23 25 45 97 112 113 114 115 139
PVDDQ_EF: R17.1 ; also on sheet 18 20 45 97 108 109 110 111 120
PVDDQ_GH: R18.1 ; also on sheet 13 15 45 97 104 105 106 107 120
CLK_100M_CPU1_BCLK0_DN: CPU2.CN41(BCLK0_DN) ; also on sheet 56
CLK_100M_CPU1_BCLK0_DP: CPU2.CL41(BCLK0_DP) ; also on sheet 56
CLK_100M_CPU1_BCLK1_DN: CPU2.AW45(BCLK1_DN) ; also on sheet 56
CLK_100M_CPU1_BCLK1_DP: CPU2.BA45(BCLK1_DP) ; also on sheet 56
FM_CPU1_BDX_PRSNT_LVT3_N: CPU2.AB48(PROC_ID) ; also on sheet 51 179
FM_CPU1_SKTOCC_BMC_LVT3_N: R1139.2 ; also on sheet 180
FM_CPU1_SKTOCC_LVT3_N: CPU2.BU49(SKTOCC#) R1139.1 ; also on sheet 46 51 179
H_CPU1_CATERR_G_N: CPU2.CC51(CATERR#) ; also on sheet 100
H_CPU1_ERR0_G_N: CPU2.BD50(ERROR_N0) ; also on sheet 102
H_CPU1_ERR1_G_N: CPU2.BB48(ERROR_N1) ; also on sheet 102
H_CPU1_ERR2_G_N: CPU2.BB52(ERROR_N2) ; also on sheet 102
H_CPU1_FAST_WAKE_G_N: CPU2.AV44(PM_FAST_WAKE#) ; also on sheet 179
H_CPU1_FIVR_FAULT_G: CPU2.CY40(FIVR_FAULT) ; also on sheet 101 179
H_CPU1_MEMEF_MEMHOT_G_N: CPU2.CL33(MEM_HOT_C1#) ; also on sheet 101 181 183
H_CPU1_MEMGH_MEMHOT_G_N: CPU2.P36(MEM_HOT_C23#) ; also on sheet 101 181 183
H_CPU1_MSMI_G_N: CPU2.H52(MSMI#) ; also on sheet 179
H_CPU1_PROCHOT_G_N: CPU2.BL51(PROCHOT#) ; also on sheet 101 181 183
H_CPU1_THERMTRIP_G_N: CPU2.BJ47(THERMTRIP#) ; also on sheet 101 179
H_PM_SYNC_G: CPU2.K52(PMSYNC) ; also on sheet 91 139
M_E_ACT_N: CPU2.CK16(DDR0_ACT#) ; also on sheet 110 111
M_E_ALERT_N: CPU2.CD16(DDR0_ALERT#) ; also on sheet 110 111
M_E_BA_0: CPU2.CL21(DDR0_BA0) ; also on sheet 110 111
M_E_BA_1: CPU2.CH20(DDR0_BA1) ; also on sheet 110 111
M_E_BG_0: CPU2.CL17(DDR0_BG0) ; also on sheet 110 111
M_E_BG_1: CPU2.CN17(DDR0_BG1) ; also on sheet 110 111
M_E_C_2: CPU2.CJ25(DDR0_CID2) ; also on sheet 110 111
M_E_CKE_0: CPU2.CJ17(DDR0_CKE0) ; also on sheet 111
M_E_CKE_1: CPU2.CE17(DDR0_CKE1) ; also on sheet 111
M_E_CKE_2: CPU2.CF16(DDR0_CKE2) ; also on sheet 110
M_E_CKE_3: CPU2.CC17(DDR0_CKE3) ; also on sheet 110
M_E_CLK_DN_0: CPU2.CE21(DDR0_CLK_DN0) ; also on sheet 111
M_E_CLK_DN_1: CPU2.CF18(DDR0_CLK_DN1) ; also on sheet 110
M_E_CLK_DN_2: CPU2.CF20(DDR0_CLK_DN2) ; also on sheet 111
M_E_CLK_DN_3: CPU2.CE19(DDR0_CLK_DN3) ; also on sheet 110
M_E_CLK_DP_0: CPU2.CC21(DDR0_CLK_DP0) ; also on sheet 111
M_E_CLK_DP_1: CPU2.CD18(DDR0_CLK_DP1) ; also on sheet 110
M_E_CLK_DP_2: CPU2.CD20(DDR0_CLK_DP2) ; also on sheet 111
M_E_CLK_DP_3: CPU2.CC19(DDR0_CLK_DP3) ; also on sheet 110
M_E_CS_N_0: CPU2.CD22(DDR0_CS0#) ; also on sheet 111
M_E_CS_N_1: CPU2.CH22(DDR0_CS1#) ; also on sheet 111
M_E_CS_N_2: CPU2.CF26(DDR0_CS2#/CID0) ; also on sheet 111
M_E_CS_N_3: CPU2.CC25(DDR0_CS3#/CID1) ; also on sheet 111
M_E_CS_N_4: CPU2.CK22(DDR0_CS4#) ; also on sheet 110
M_E_CS_N_5: CPU2.CH24(DDR0_CS5#) ; also on sheet 110
M_E_CS_N_6: CPU2.CH26(DDR0_CS6#/CID3) ; also on sheet 110
M_E_CS_N_7: CPU2.CD26(DDR0_CS7#/CID4) ; also on sheet 110
M_E_DQ_0: CPU2.BU7(DDR0_DQ0) ; also on sheet 110 111
M_E_DQ_1: CPU2.BT6(DDR0_DQ1) ; also on sheet 110 111
M_E_DQ_2: CPU2.CA9(DDR0_DQ2) ; also on sheet 110 111
M_E_DQ_3: CPU2.CB8(DDR0_DQ3) ; also on sheet 110 111
M_E_DQ_4: CPU2.BT8(DDR0_DQ4) ; also on sheet 110 111
M_E_DQ_5: CPU2.BU9(DDR0_DQ5) ; also on sheet 110 111
M_E_DQ_6: CPU2.CA7(DDR0_DQ6) ; also on sheet 110 111
M_E_DQ_7: CPU2.CB6(DDR0_DQ7) ; also on sheet 110 111
M_E_DQ_8: CPU2.BT12(DDR0_DQ8) ; also on sheet 110 111
M_E_DQ_9: CPU2.BU11(DDR0_DQ9) ; also on sheet 110 111
M_E_DQ_10: CPU2.BW13(DDR0_DQ10) ; also on sheet 110 111
M_E_DQ_11: CPU2.BY14(DDR0_DQ11) ; also on sheet 110 111
M_E_DQ_12: CPU2.BT14(DDR0_DQ12) ; also on sheet 110 111
M_E_DQ_13: CPU2.BU15(DDR0_DQ13) ; also on sheet 110 111
M_E_DQ_14: CPU2.CA11(DDR0_DQ14) ; also on sheet 110 111
M_E_DQ_15: CPU2.BY12(DDR0_DQ15) ; also on sheet 110 111
M_E_DQ_16: CPU2.CE9(DDR0_DQ16) ; also on sheet 110 111
M_E_DQ_17: CPU2.CF8(DDR0_DQ17) ; also on sheet 110 111
M_E_DQ_18: CPU2.CK10(DDR0_DQ18) ; also on sheet 110 111
M_E_DQ_19: CPU2.CJ11(DDR0_DQ19) ; also on sheet 110 111
M_E_DQ_20: CPU2.CD10(DDR0_DQ20) ; also on sheet 110 111
M_E_DQ_21: CPU2.CE11(DDR0_DQ21) ; also on sheet 110 111
M_E_DQ_22: CPU2.CK8(DDR0_DQ22) ; also on sheet 110 111
M_E_DQ_23: CPU2.CJ9(DDR0_DQ23) ; also on sheet 110 111
M_E_DQ_24: CPU2.CE13(DDR0_DQ24) ; also on sheet 110 111
M_E_DQ_25: CPU2.CG15(DDR0_DQ25) ; also on sheet 110 111
M_E_DQ_26: CPU2.CM14(DDR0_DQ26) ; also on sheet 110 111
M_E_DQ_27: CPU2.CH14(DDR0_DQ27) ; also on sheet 110 111
M_E_DQ_28: CPU2.CC13(DDR0_DQ28) ; also on sheet 110 111
M_E_DQ_29: CPU2.CD14(DDR0_DQ29) ; also on sheet 110 111
M_E_DQ_30: CPU2.CM12(DDR0_DQ30) ; also on sheet 110 111
M_E_DQ_31: CPU2.CL13(DDR0_DQ31) ; also on sheet 110 111
M_E_DQ_32: CPU2.CK28(DDR0_DQ32) ; also on sheet 110 111
M_E_DQ_33: CPU2.CH28(DDR0_DQ33) ; also on sheet 110 111
M_E_DQ_34: CPU2.CK32(DDR0_DQ34) ; also on sheet 110 111
M_E_DQ_35: CPU2.CH32(DDR0_DQ35) ; also on sheet 110 111
M_E_DQ_36: CPU2.CL27(DDR0_DQ36) ; also on sheet 110 111
M_E_DQ_37: CPU2.CJ27(DDR0_DQ37) ; also on sheet 110 111
M_E_DQ_38: CPU2.CL31(DDR0_DQ38) ; also on sheet 110 111
M_E_DQ_39: CPU2.CJ31(DDR0_DQ39) ; also on sheet 110 111
M_E_DQ_40: CPU2.CD28(DDR0_DQ40) ; also on sheet 110 111
M_E_DQ_41: CPU2.CB28(DDR0_DQ41) ; also on sheet 110 111
M_E_DQ_42: CPU2.CD32(DDR0_DQ42) ; also on sheet 110 111
M_E_DQ_43: CPU2.CB32(DDR0_DQ43) ; also on sheet 110 111
M_E_DQ_44: CPU2.CE27(DDR0_DQ44) ; also on sheet 110 111
M_E_DQ_45: CPU2.CC27(DDR0_DQ45) ; also on sheet 110 111
M_E_DQ_46: CPU2.CE31(DDR0_DQ46) ; also on sheet 110 111
M_E_DQ_47: CPU2.CC31(DDR0_DQ47) ; also on sheet 110 111
M_E_DQ_48: CPU2.CE35(DDR0_DQ48) ; also on sheet 110 111
M_E_DQ_49: CPU2.CC35(DDR0_DQ49) ; also on sheet 110 111
M_E_DQ_50: CPU2.CE39(DDR0_DQ50) ; also on sheet 110 111
M_E_DQ_51: CPU2.CC39(DDR0_DQ51) ; also on sheet 110 111
M_E_DQ_52: CPU2.CF34(DDR0_DQ52) ; also on sheet 110 111
M_E_DQ_53: CPU2.CD34(DDR0_DQ53) ; also on sheet 110 111
M_E_DQ_54: CPU2.CF38(DDR0_DQ54) ; also on sheet 110 111
M_E_DQ_55: CPU2.CD38(DDR0_DQ55) ; also on sheet 110 111
M_E_DQ_56: CPU2.CL35(DDR0_DQ56) ; also on sheet 110 111
M_E_DQ_57: CPU2.CJ35(DDR0_DQ57) ; also on sheet 110 111
M_E_DQ_58: CPU2.CL39(DDR0_DQ58) ; also on sheet 110 111
M_E_DQ_59: CPU2.CJ39(DDR0_DQ59) ; also on sheet 110 111
M_E_DQ_60: CPU2.CM34(DDR0_DQ60) ; also on sheet 110 111
M_E_DQ_61: CPU2.CK34(DDR0_DQ61) ; also on sheet 110 111
M_E_DQ_62: CPU2.CM38(DDR0_DQ62) ; also on sheet 110 111
M_E_DQ_63: CPU2.CK38(DDR0_DQ63) ; also on sheet 110 111
M_E_DQS_DN_0: CPU2.BV6(DDR0_DQS_DN0) ; also on sheet 110 111
M_E_DQS_DN_1: CPU2.BW11(DDR0_DQS_DN1) ; also on sheet 110 111
M_E_DQS_DN_2: CPU2.CG11(DDR0_DQS_DN2) ; also on sheet 110 111
M_E_DQS_DN_3: CPU2.CJ13(DDR0_DQS_DN3) ; also on sheet 110 111
M_E_DQS_DN_4: CPU2.CM30(DDR0_DQS_DN4) ; also on sheet 110 111
M_E_DQS_DN_5: CPU2.CF30(DDR0_DQS_DN5) ; also on sheet 110 111
M_E_DQS_DN_6: CPU2.CE37(DDR0_DQS_DN6) ; also on sheet 110 111
M_E_DQS_DN_7: CPU2.CL37(DDR0_DQS_DN7) ; also on sheet 110 111
M_E_DQS_DN_8: CPU2.CT10(DDR0_DQS_DN8) ; also on sheet 110 111
M_E_DQS_DN_9: CPU2.BW9(DDR0_DQS_DN9) ; also on sheet 110 111
M_E_DQS_DN_10: CPU2.BV14(DDR0_DQS_DN10) ; also on sheet 110 111
M_E_DQS_DN_11: CPU2.CH8(DDR0_DQS_DN11) ; also on sheet 110 111
M_E_DQS_DN_12: CPU2.CF14(DDR0_DQS_DN12) ; also on sheet 110 111
M_E_DQS_DN_13: CPU2.CJ29(DDR0_DQS_DN13) ; also on sheet 110 111
M_E_DQS_DN_14: CPU2.CC29(DDR0_DQS_DN14) ; also on sheet 110 111
M_E_DQS_DN_15: CPU2.CD36(DDR0_DQS_DN15) ; also on sheet 110 111
M_E_DQS_DN_16: CPU2.CK36(DDR0_DQS_DN16) ; also on sheet 110 111
M_E_DQS_DN_17: CPU2.CW9(DDR0_DQS_DN17) ; also on sheet 110 111
M_E_DQS_DP_0: CPU2.BY6(DDR0_DQS_DP0) ; also on sheet 110 111
M_E_DQS_DP_1: CPU2.BV12(DDR0_DQS_DP1) ; also on sheet 110 111
M_E_DQS_DP_2: CPU2.CH10(DDR0_DQS_DP2) ; also on sheet 110 111
M_E_DQS_DP_3: CPU2.CK14(DDR0_DQS_DP3) ; also on sheet 110 111
M_E_DQS_DP_4: CPU2.CK30(DDR0_DQS_DP4) ; also on sheet 110 111
M_E_DQS_DP_5: CPU2.CD30(DDR0_DQS_DP5) ; also on sheet 110 111
M_E_DQS_DP_6: CPU2.CC37(DDR0_DQS_DP6) ; also on sheet 110 111
M_E_DQS_DP_7: CPU2.CJ37(DDR0_DQS_DP7) ; also on sheet 110 111
M_E_DQS_DP_8: CPU2.CV10(DDR0_DQS_DP8) ; also on sheet 110 111
M_E_DQS_DP_9: CPU2.BV8(DDR0_DQS_DP9) ; also on sheet 110 111
M_E_DQS_DP_10: CPU2.BU13(DDR0_DQS_DP10) ; also on sheet 110 111
M_E_DQS_DP_11: CPU2.CG9(DDR0_DQS_DP11) ; also on sheet 110 111
M_E_DQS_DP_12: CPU2.CG13(DDR0_DQS_DP12) ; also on sheet 110 111
M_E_DQS_DP_13: CPU2.CL29(DDR0_DQS_DP13) ; also on sheet 110 111
M_E_DQS_DP_14: CPU2.CE29(DDR0_DQS_DP14) ; also on sheet 110 111
M_E_DQS_DP_15: CPU2.CF36(DDR0_DQS_DP15) ; also on sheet 110 111
M_E_DQS_DP_16: CPU2.CM36(DDR0_DQS_DP16) ; also on sheet 110 111
M_E_DQS_DP_17: CPU2.CU9(DDR0_DQS_DP17) ; also on sheet 110 111
M_E_ECC_0: CPU2.CT8(DDR0_ECC0) ; also on sheet 110 111
M_E_ECC_1: CPU2.CV8(DDR0_ECC1) ; also on sheet 110 111
M_E_ECC_2: CPU2.CW11(DDR0_ECC2) ; also on sheet 110 111
M_E_ECC_3: CPU2.CU11(DDR0_ECC3) ; also on sheet 110 111
M_E_ECC_4: CPU2.CP8(DDR0_ECC4) ; also on sheet 110 111
M_E_ECC_5: CPU2.CN9(DDR0_ECC5) ; also on sheet 110 111
M_E_ECC_6: CPU2.CP10(DDR0_ECC6) ; also on sheet 110 111
M_E_ECC_7: CPU2.CR11(DDR0_ECC7) ; also on sheet 110 111
M_E_MA_0: CPU2.CP22(DDR0_MA0) ; also on sheet 110 111
M_E_MA_1: CPU2.CR21(DDR0_MA1) ; also on sheet 110 111
M_E_MA_2: CPU2.CT22(DDR0_MA2) ; also on sheet 110 111
M_E_MA_3: CPU2.CN21(DDR0_MA3) ; also on sheet 110 111
M_E_MA_4: CPU2.CP20(DDR0_MA4) ; also on sheet 110 111
M_E_MA_5: CPU2.CL19(DDR0_MA5) ; also on sheet 110 111
M_E_MA_6: CPU2.CN19(DDR0_MA6) ; also on sheet 110 111
M_E_MA_7: CPU2.CH18(DDR0_MA7) ; also on sheet 110 111
M_E_MA_8: CPU2.CJ19(DDR0_MA8) ; also on sheet 110 111
M_E_MA_9: CPU2.CK18(DDR0_MA9) ; also on sheet 110 111
M_E_MA_10: CPU2.CP24(DDR0_MA10) ; also on sheet 110 111
M_E_MA_11: CPU2.CP18(DDR0_MA11) ; also on sheet 110 111
M_E_MA_12: CPU2.CR17(DDR0_MA12) ; also on sheet 110 111
M_E_MA_13: CPU2.CE23(DDR0_MA13) ; also on sheet 110 111
M_E_MA_14: CPU2.CJ21(DDR0_MA14) ; also on sheet 110 111
M_E_MA_15: CPU2.CL25(DDR0_MA15) ; also on sheet 110 111
M_E_MA_16: CPU2.CL23(DDR0_MA16) ; also on sheet 110 111
M_E_MA_17: CPU2.CD24(DDR0_MA17) ; also on sheet 110 111
M_E_ODT_0: CPU2.CF22(DDR0_ODT0) ; also on sheet 111
M_E_ODT_1: CPU2.CN25(DDR0_ODT1) ; also on sheet 111
M_E_ODT_2: CPU2.CJ23(DDR0_ODT2) ; also on sheet 110
M_E_ODT_3: CPU2.CC23(DDR0_ODT3) ; also on sheet 110
M_E_PAR: CPU2.CK20(DDR0_PAR) ; also on sheet 110 111
M_EF_CPU_VREF: C862.1 CPU2.BY16(DDR1_VREF) R19.1
M_EF_RESET_N: CPU2.DC15(DDR_RESET_C1#) ; also on sheet 108 109 110 111
M_EF_VREF: R17.2 R19.2 R21.1 ; also on sheet 108 109 110 111
M_F_ACT_N: CPU2.CT16(DDR1_ACT#) ; also on sheet 108 109
M_F_ALERT_N: CPU2.CR15(DDR1_ALERT#) ; also on sheet 108 109
M_F_BA_0: CPU2.CW23(DDR1_BA0) ; also on sheet 108 109
M_F_BA_1: CPU2.CV22(DDR1_BA1) ; also on sheet 108 109
M_F_BG_0: CPU2.CV16(DDR1_BG0) ; also on sheet 108 109
M_F_BG_1: CPU2.CP16(DDR1_BG1) ; also on sheet 108 109
M_F_C_2: CPU2.CR25(DDR1_CID2) ; also on sheet 108 109
M_F_CKE_0: CPU2.DA17(DDR1_CKE0) ; also on sheet 109
M_F_CKE_1: CPU2.DC17(DDR1_CKE1) ; also on sheet 109
M_F_CKE_2: CPU2.DD16(DDR1_CKE2) ; also on sheet 108
M_F_CKE_3: CPU2.DF16(DDR1_CKE3) ; also on sheet 108
M_F_CLK_DN_0: CPU2.DC21(DDR1_CLK_DN0) ; also on sheet 109
M_F_CLK_DN_1: CPU2.DD18(DDR1_CLK_DN1) ; also on sheet 108
M_F_CLK_DN_2: CPU2.DD20(DDR1_CLK_DN2) ; also on sheet 109
M_F_CLK_DN_3: CPU2.DC19(DDR1_CLK_DN3) ; also on sheet 108
M_F_CLK_DP_0: CPU2.DE21(DDR1_CLK_DP0) ; also on sheet 109
M_F_CLK_DP_1: CPU2.DF18(DDR1_CLK_DP1) ; also on sheet 108
M_F_CLK_DP_2: CPU2.DF20(DDR1_CLK_DP2) ; also on sheet 109
M_F_CLK_DP_3: CPU2.DE19(DDR1_CLK_DP3) ; also on sheet 108
M_F_CS_N_0: CPU2.DF22(DDR1_CS0#) ; also on sheet 109
M_F_CS_N_1: CPU2.DE23(DDR1_CS1#) ; also on sheet 109
M_F_CS_N_2: CPU2.CT26(DDR1_CS2#/CID0) ; also on sheet 109
M_F_CS_N_3: CPU2.CP26(DDR1_CS3#/CID1) ; also on sheet 109
M_F_CS_N_4: CPU2.DA23(DDR1_CS4#) ; also on sheet 108
M_F_CS_N_5: CPU2.DD24(DDR1_CS5#) ; also on sheet 108
M_F_CS_N_6: CPU2.CY26(DDR1_CS6#/CID3) ; also on sheet 108
M_F_CS_N_7: CPU2.CV26(DDR1_CS7#/CID4) ; also on sheet 108
M_F_DQ_0: CPU2.BV4(DDR1_DQ0) ; also on sheet 108 109
M_F_DQ_1: CPU2.BU1(DDR1_DQ1) ; also on sheet 108 109
M_F_DQ_2: CPU2.CA3(DDR1_DQ2) ; also on sheet 108 109
M_F_DQ_3: CPU2.CB4(DDR1_DQ3) ; also on sheet 108 109
M_F_DQ_4: CPU2.BT4(DDR1_DQ4) ; also on sheet 108 109
M_F_DQ_5: CPU2.BT2(DDR1_DQ5) ; also on sheet 108 109
M_F_DQ_6: CPU2.CA1(DDR1_DQ6) ; also on sheet 108 109
M_F_DQ_7: CPU2.BY2(DDR1_DQ7) ; also on sheet 108 109
M_F_DQ_8: CPU2.CE3(DDR1_DQ8) ; also on sheet 108 109
M_F_DQ_9: CPU2.CF4(DDR1_DQ9) ; also on sheet 108 109
M_F_DQ_10: CPU2.CL5(DDR1_DQ10) ; also on sheet 108 109
M_F_DQ_11: CPU2.CM4(DDR1_DQ11) ; also on sheet 108 109
M_F_DQ_12: CPU2.CE5(DDR1_DQ12) ; also on sheet 108 109
M_F_DQ_13: CPU2.CF6(DDR1_DQ13) ; also on sheet 108 109
M_F_DQ_14: CPU2.CK6(DDR1_DQ14) ; also on sheet 108 109
M_F_DQ_15: CPU2.CL3(DDR1_DQ15) ; also on sheet 108 109
M_F_DQ_16: CPU2.CR3(DDR1_DQ16) ; also on sheet 108 109
M_F_DQ_17: CPU2.CV2(DDR1_DQ17) ; also on sheet 108 109
M_F_DQ_18: CPU2.CT6(DDR1_DQ18) ; also on sheet 108 109
M_F_DQ_19: CPU2.CP6(DDR1_DQ19) ; also on sheet 108 109
M_F_DQ_20: CPU2.CR1(DDR1_DQ20) ; also on sheet 108 109
M_F_DQ_21: CPU2.CP2(DDR1_DQ21) ; also on sheet 108 109
M_F_DQ_22: CPU2.CU5(DDR1_DQ22) ; also on sheet 108 109
M_F_DQ_23: CPU2.CR5(DDR1_DQ23) ; also on sheet 108 109
M_F_DQ_24: CPU2.DA7(DDR1_DQ24) ; also on sheet 108 109
M_F_DQ_25: CPU2.DB8(DDR1_DQ25) ; also on sheet 108 109
M_F_DQ_26: CPU2.DE11(DDR1_DQ26) ; also on sheet 108 109
M_F_DQ_27: CPU2.DC11(DDR1_DQ27) ; also on sheet 108 109
M_F_DQ_28: CPU2.DA5(DDR1_DQ28) ; also on sheet 108 109
M_F_DQ_29: CPU2.CY6(DDR1_DQ29) ; also on sheet 108 109
M_F_DQ_30: CPU2.DE9(DDR1_DQ30) ; also on sheet 108 109
M_F_DQ_31: CPU2.DF10(DDR1_DQ31) ; also on sheet 108 109
M_F_DQ_32: CPU2.CT28(DDR1_DQ32) ; also on sheet 108 109
M_F_DQ_33: CPU2.CP28(DDR1_DQ33) ; also on sheet 108 109
M_F_DQ_34: CPU2.CT32(DDR1_DQ34) ; also on sheet 108 109
M_F_DQ_35: CPU2.CP32(DDR1_DQ35) ; also on sheet 108 109
M_F_DQ_36: CPU2.CU27(DDR1_DQ36) ; also on sheet 108 109
M_F_DQ_37: CPU2.CR27(DDR1_DQ37) ; also on sheet 108 109
M_F_DQ_38: CPU2.CU31(DDR1_DQ38) ; also on sheet 108 109
M_F_DQ_39: CPU2.CR31(DDR1_DQ39) ; also on sheet 108 109
M_F_DQ_40: CPU2.DA29(DDR1_DQ40) ; also on sheet 108 109
M_F_DQ_41: CPU2.DB30(DDR1_DQ41) ; also on sheet 108 109
M_F_DQ_42: CPU2.DC33(DDR1_DQ42) ; also on sheet 108 109
M_F_DQ_43: CPU2.DF34(DDR1_DQ43) ; also on sheet 108 109
M_F_DQ_44: CPU2.DB28(DDR1_DQ44) ; also on sheet 108 109
M_F_DQ_45: CPU2.CY28(DDR1_DQ45) ; also on sheet 108 109
M_F_DQ_46: CPU2.DA33(DDR1_DQ46) ; also on sheet 108 109
M_F_DQ_47: CPU2.DE33(DDR1_DQ47) ; also on sheet 108 109
M_F_DQ_48: CPU2.CU35(DDR1_DQ48) ; also on sheet 108 109
M_F_DQ_49: CPU2.CR35(DDR1_DQ49) ; also on sheet 108 109
M_F_DQ_50: CPU2.CU39(DDR1_DQ50) ; also on sheet 108 109
M_F_DQ_51: CPU2.CR39(DDR1_DQ51) ; also on sheet 108 109
M_F_DQ_52: CPU2.CV34(DDR1_DQ52) ; also on sheet 108 109
M_F_DQ_53: CPU2.CT34(DDR1_DQ53) ; also on sheet 108 109
M_F_DQ_54: CPU2.CV38(DDR1_DQ54) ; also on sheet 108 109
M_F_DQ_55: CPU2.CT38(DDR1_DQ55) ; also on sheet 108 109
M_F_DQ_56: CPU2.DC37(DDR1_DQ56) ; also on sheet 108 109
M_F_DQ_57: CPU2.DF36(DDR1_DQ57) ; also on sheet 108 109
M_F_DQ_58: CPU2.DC39(DDR1_DQ58) ; also on sheet 108 109
M_F_DQ_59: CPU2.DA39(DDR1_DQ59) ; also on sheet 108 109
M_F_DQ_60: CPU2.DC35(DDR1_DQ60) ; also on sheet 108 109
M_F_DQ_61: CPU2.DB36(DDR1_DQ61) ; also on sheet 108 109
M_F_DQ_62: CPU2.DF38(DDR1_DQ62) ; also on sheet 108 109
M_F_DQ_63: CPU2.DE39(DDR1_DQ63) ; also on sheet 108 109
M_F_DQS_DN_0: CPU2.BW3(DDR1_DQS_DN0) ; also on sheet 108 109
M_F_DQS_DN_1: CPU2.CH6(DDR1_DQS_DN1) ; also on sheet 108 109
M_F_DQS_DN_2: CPU2.CV4(DDR1_DQS_DN2) ; also on sheet 108 109
M_F_DQS_DN_3: CPU2.DC9(DDR1_DQS_DN3) ; also on sheet 108 109
M_F_DQS_DN_4: CPU2.CV30(DDR1_DQS_DN4) ; also on sheet 108 109
M_F_DQS_DN_5: CPU2.DB32(DDR1_DQS_DN5) ; also on sheet 108 109
M_F_DQS_DN_6: CPU2.CU37(DDR1_DQS_DN6) ; also on sheet 108 109
M_F_DQS_DN_7: CPU2.DA37(DDR1_DQS_DN7) ; also on sheet 108 109
M_F_DQS_DN_8: CPU2.DA13(DDR1_DQS_DN8) ; also on sheet 108 109
M_F_DQS_DN_9: CPU2.BW1(DDR1_DQS_DN9) ; also on sheet 108 109
M_F_DQS_DN_10: CPU2.CG3(DDR1_DQS_DN10) ; also on sheet 108 109
M_F_DQS_DN_11: CPU2.CU3(DDR1_DQS_DN11) ; also on sheet 108 109
M_F_DQS_DN_12: CPU2.DD8(DDR1_DQS_DN12) ; also on sheet 108 109
M_F_DQS_DN_13: CPU2.CR29(DDR1_DQS_DN13) ; also on sheet 108 109
M_F_DQS_DN_14: CPU2.CY32(DDR1_DQS_DN14) ; also on sheet 108 109
M_F_DQS_DN_15: CPU2.CT36(DDR1_DQS_DN15) ; also on sheet 108 109
M_F_DQS_DN_16: CPU2.DE37(DDR1_DQS_DN16) ; also on sheet 108 109
M_F_DQS_DN_17: CPU2.CY14(DDR1_DQS_DN17) ; also on sheet 108 109
M_F_DQS_DP_0: CPU2.BY4(DDR1_DQS_DP0) ; also on sheet 108 109
M_F_DQS_DP_1: CPU2.CJ5(DDR1_DQS_DP1) ; also on sheet 108 109
M_F_DQS_DP_2: CPU2.CT4(DDR1_DQS_DP2) ; also on sheet 108 109
M_F_DQS_DP_3: CPU2.DB10(DDR1_DQS_DP3) ; also on sheet 108 109
M_F_DQS_DP_4: CPU2.CT30(DDR1_DQS_DP4) ; also on sheet 108 109
M_F_DQS_DP_5: CPU2.DD32(DDR1_DQS_DP5) ; also on sheet 108 109
M_F_DQS_DP_6: CPU2.CR37(DDR1_DQS_DP6) ; also on sheet 108 109
M_F_DQS_DP_7: CPU2.DB38(DDR1_DQS_DP7) ; also on sheet 108 109
M_F_DQS_DP_8: CPU2.DB14(DDR1_DQS_DP8) ; also on sheet 108 109
M_F_DQS_DP_9: CPU2.BV2(DDR1_DQS_DP9) ; also on sheet 108 109
M_F_DQS_DP_10: CPU2.CH4(DDR1_DQS_DP10) ; also on sheet 108 109
M_F_DQS_DP_11: CPU2.CW3(DDR1_DQS_DP11) ; also on sheet 108 109
M_F_DQS_DP_12: CPU2.DC7(DDR1_DQS_DP12) ; also on sheet 108 109
M_F_DQS_DP_13: CPU2.CU29(DDR1_DQS_DP13) ; also on sheet 108 109
M_F_DQS_DP_14: CPU2.DA31(DDR1_DQS_DP14) ; also on sheet 108 109
M_F_DQS_DP_15: CPU2.CV36(DDR1_DQS_DP15) ; also on sheet 108 109
M_F_DQS_DP_16: CPU2.DD36(DDR1_DQS_DP16) ; also on sheet 108 109
M_F_DQS_DP_17: CPU2.CW13(DDR1_DQS_DP17) ; also on sheet 108 109
M_F_ECC_0: CPU2.CU13(DDR1_ECC0) ; also on sheet 108 109
M_F_ECC_1: CPU2.CV14(DDR1_ECC1) ; also on sheet 108 109
M_F_ECC_2: CPU2.DD14(DDR1_ECC2) ; also on sheet 108 109
M_F_ECC_3: CPU2.DF14(DDR1_ECC3) ; also on sheet 108 109
M_F_ECC_4: CPU2.CR13(DDR1_ECC4) ; also on sheet 108 109
M_F_ECC_5: CPU2.CT14(DDR1_ECC5) ; also on sheet 108 109
M_F_ECC_6: CPU2.DC13(DDR1_ECC6) ; also on sheet 108 109
M_F_ECC_7: CPU2.DE13(DDR1_ECC7) ; also on sheet 108 109
M_F_MA_0: CPU2.CY22(DDR1_MA0) ; also on sheet 108 109
M_F_MA_1: CPU2.DA21(DDR1_MA1) ; also on sheet 108 109
M_F_MA_2: CPU2.CV20(DDR1_MA2) ; also on sheet 108 109
M_F_MA_3: CPU2.CW21(DDR1_MA3) ; also on sheet 108 109
M_F_MA_4: CPU2.CR19(DDR1_MA4) ; also on sheet 108 109
M_F_MA_5: CPU2.CY20(DDR1_MA5) ; also on sheet 108 109
M_F_MA_6: CPU2.CW19(DDR1_MA6) ; also on sheet 108 109
M_F_MA_7: CPU2.CT18(DDR1_MA7) ; also on sheet 108 109
M_F_MA_8: CPU2.DA19(DDR1_MA8) ; also on sheet 108 109
M_F_MA_9: CPU2.CY18(DDR1_MA9) ; also on sheet 108 109
M_F_MA_10: CPU2.CR23(DDR1_MA10) ; also on sheet 108 109
M_F_MA_11: CPU2.CV18(DDR1_MA11) ; also on sheet 108 109
M_F_MA_12: CPU2.CW17(DDR1_MA12) ; also on sheet 108 109
M_F_MA_13: CPU2.CW25(DDR1_MA13) ; also on sheet 108 109
M_F_MA_14: CPU2.CN23(DDR1_MA14) ; also on sheet 108 109
M_F_MA_15: CPU2.CV24(DDR1_MA15) ; also on sheet 108 109
M_F_MA_16: CPU2.CY24(DDR1_MA16) ; also on sheet 108 109
M_F_MA_17: CPU2.CT24(DDR1_MA17) ; also on sheet 108 109
M_F_ODT_0: CPU2.DD22(DDR1_ODT0) ; also on sheet 109
M_F_ODT_1: CPU2.DE25(DDR1_ODT1) ; also on sheet 109
M_F_ODT_2: CPU2.DC23(DDR1_ODT2) ; also on sheet 108
M_F_ODT_3: CPU2.DC25(DDR1_ODT3) ; also on sheet 108
M_F_PAR: CPU2.CT20(DDR1_PAR) ; also on sheet 108 109
M_GH_CPU_VREF: C863.1 CPU2.T40(DDR23_VREF) R20.1
M_GH_RESET_N: CPU2.C23(DDR_RESET_C23#) ; also on sheet 104 105 106 107
M_GH_VREF: R18.2 R20.2 R22.1 ; also on sheet 104 105 106 107
P3E_CPU0_PE3_MEZZ_RX_DN_8: CPU1.AF48(PE3C_RX_DN8) ; also on sheet 95
P3E_CPU0_PE3_MEZZ_RX_DN_9: CPU1.AG51(PE3C_RX_DN9) ; also on sheet 95
P3E_CPU0_PE3_MEZZ_RX_DN_10: CPU1.AF50(PE3C_RX_DN10) ; also on sheet 95
P3E_CPU0_PE3_MEZZ_RX_DN_11: CPU1.AG49(PE3C_RX_DN11) ; also on sheet 95
P3E_CPU0_PE3_MEZZ_RX_DN_12: CPU1.AG47(PE3D_RX_DN12) ; also on sheet 95
P3E_CPU0_PE3_MEZZ_RX_DN_13: CPU1.AN47(PE3D_RX_DN13) ; also on sheet 95
P3E_CPU0_PE3_MEZZ_RX_DN_14: CPU1.AM46(PE3D_RX_DN14) ; also on sheet 95
P3E_CPU0_PE3_MEZZ_RX_DN_15: CPU1.AN45(PE3D_RX_DN15) ; also on sheet 95
P3E_CPU0_PE3_MEZZ_RX_DP_8: CPU1.AH48(PE3C_RX_DP8) ; also on sheet 95
P3E_CPU0_PE3_MEZZ_RX_DP_9: CPU1.AJ51(PE3C_RX_DP9) ; also on sheet 95
P3E_CPU0_PE3_MEZZ_RX_DP_10: CPU1.AH50(PE3C_RX_DP10) ; also on sheet 95
P3E_CPU0_PE3_MEZZ_RX_DP_11: CPU1.AJ49(PE3C_RX_DP11) ; also on sheet 95
P3E_CPU0_PE3_MEZZ_RX_DP_12: CPU1.AJ47(PE3D_RX_DP12) ; also on sheet 95
P3E_CPU0_PE3_MEZZ_RX_DP_13: CPU1.AR47(PE3D_RX_DP13) ; also on sheet 95
P3E_CPU0_PE3_MEZZ_RX_DP_14: CPU1.AP46(PE3D_RX_DP14) ; also on sheet 95
P3E_CPU0_PE3_MEZZ_RX_DP_15: CPU1.AR45(PE3D_RX_DP15) ; also on sheet 95
P3E_CPU0_PE3_MEZZ_TX_DN_8: CPU1.P46(PE3C_TX_DN8) ; also on sheet 95
P3E_CPU0_PE3_MEZZ_TX_DN_9: CPU1.R45(PE3C_TX_DN9) ; also on sheet 95
P3E_CPU0_PE3_MEZZ_TX_DN_10: CPU1.AA47(PE3C_TX_DN10) ; also on sheet 95
P3E_CPU0_PE3_MEZZ_TX_DN_11: CPU1.Y46(PE3C_TX_DN11) ; also on sheet 95
P3E_CPU0_PE3_MEZZ_TX_DN_12: CPU1.AA45(PE3D_TX_DN12) ; also on sheet 95
P3E_CPU0_PE3_MEZZ_TX_DN_13: CPU1.Y44(PE3D_TX_DN13) ; also on sheet 95
P3E_CPU0_PE3_MEZZ_TX_DN_14: CPU1.AC43(PE3D_TX_DN14) ; also on sheet 95
P3E_CPU0_PE3_MEZZ_TX_DN_15: CPU1.T44(PE3D_TX_DN15) ; also on sheet 95
P3E_CPU0_PE3_MEZZ_TX_DP_8: CPU1.T46(PE3C_TX_DP8) ; also on sheet 95
P3E_CPU0_PE3_MEZZ_TX_DP_9: CPU1.U45(PE3C_TX_DP9) ; also on sheet 95
P3E_CPU0_PE3_MEZZ_TX_DP_10: CPU1.AC47(PE3C_TX_DP10) ; also on sheet 95
P3E_CPU0_PE3_MEZZ_TX_DP_11: CPU1.AB46(PE3C_TX_DP11) ; also on sheet 95
P3E_CPU0_PE3_MEZZ_TX_DP_12: CPU1.AC45(PE3D_TX_DP12) ; also on sheet 95
P3E_CPU0_PE3_MEZZ_TX_DP_13: CPU1.AB44(PE3D_TX_DP13) ; also on sheet 95
P3E_CPU0_PE3_MEZZ_TX_DP_14: CPU1.AA43(PE3D_TX_DP14) ; also on sheet 95
P3E_CPU0_PE3_MEZZ_TX_DP_15: CPU1.P44(PE3D_TX_DP15) ; also on sheet 95
P3E_CPU0_PE3_RISER2_RX_DN_0: CPU1.AF44(PE3A_RX_DN0) ; also on sheet 93
P3E_CPU0_PE3_RISER2_RX_DN_1: CPU1.AG45(PE3A_RX_DN1) ; also on sheet 93
P3E_CPU0_PE3_RISER2_RX_DN_2: CPU1.AF46(PE3A_RX_DN2) ; also on sheet 93
P3E_CPU0_PE3_RISER2_RX_DN_3: CPU1.AA49(PE3A_RX_DN3) ; also on sheet 93
P3E_CPU0_PE3_RISER2_RX_DN_4: CPU1.Y50(PE3B_RX_DN4) ; also on sheet 93
P3E_CPU0_PE3_RISER2_RX_DN_5: CPU1.Y52(PE3B_RX_DN5) ; also on sheet 93
P3E_CPU0_PE3_RISER2_RX_DN_6: CPU1.AA53(PE3B_RX_DN6) ; also on sheet 93
P3E_CPU0_PE3_RISER2_RX_DN_7: CPU1.AA51(PE3B_RX_DN7) ; also on sheet 93
P3E_CPU0_PE3_RISER2_RX_DP_0: CPU1.AH44(PE3A_RX_DP0) ; also on sheet 93
P3E_CPU0_PE3_RISER2_RX_DP_1: CPU1.AJ45(PE3A_RX_DP1) ; also on sheet 93
P3E_CPU0_PE3_RISER2_RX_DP_2: CPU1.AH46(PE3A_RX_DP2) ; also on sheet 93
P3E_CPU0_PE3_RISER2_RX_DP_3: CPU1.AC49(PE3A_RX_DP3) ; also on sheet 93
P3E_CPU0_PE3_RISER2_RX_DP_4: CPU1.AB50(PE3B_RX_DP4) ; also on sheet 93
P3E_CPU0_PE3_RISER2_RX_DP_5: CPU1.AB52(PE3B_RX_DP5) ; also on sheet 93
P3E_CPU0_PE3_RISER2_RX_DP_6: CPU1.AC53(PE3B_RX_DP6) ; also on sheet 93
P3E_CPU0_PE3_RISER2_RX_DP_7: CPU1.AC51(PE3B_RX_DP7) ; also on sheet 93
P3E_CPU0_PE3_RISER2_TX_DN_0: CPU1.H50(PE3A_TX_DN0) ; also on sheet 93
P3E_CPU0_PE3_RISER2_TX_DN_1: CPU1.J51(PE3A_TX_DN1) ; also on sheet 93
P3E_CPU0_PE3_RISER2_TX_DN_2: CPU1.R47(PE3A_TX_DN2) ; also on sheet 93
P3E_CPU0_PE3_RISER2_TX_DN_3: CPU1.P48(PE3A_TX_DN3) ; also on sheet 93
P3E_CPU0_PE3_RISER2_TX_DN_4: CPU1.P52(PE3B_TX_DN4) ; also on sheet 93
P3E_CPU0_PE3_RISER2_TX_DN_5: CPU1.R51(PE3B_TX_DN5) ; also on sheet 93
P3E_CPU0_PE3_RISER2_TX_DN_6: CPU1.P50(PE3B_TX_DN6) ; also on sheet 93
P3E_CPU0_PE3_RISER2_TX_DN_7: CPU1.R49(PE3B_TX_DN7) ; also on sheet 93
P3E_CPU0_PE3_RISER2_TX_DP_0: CPU1.K50(PE3A_TX_DP0) ; also on sheet 93
P3E_CPU0_PE3_RISER2_TX_DP_1: CPU1.L51(PE3A_TX_DP1) ; also on sheet 93
P3E_CPU0_PE3_RISER2_TX_DP_2: CPU1.U47(PE3A_TX_DP2) ; also on sheet 93
P3E_CPU0_PE3_RISER2_TX_DP_3: CPU1.T48(PE3A_TX_DP3) ; also on sheet 93
P3E_CPU0_PE3_RISER2_TX_DP_4: CPU1.T52(PE3B_TX_DP4) ; also on sheet 93
P3E_CPU0_PE3_RISER2_TX_DP_5: CPU1.U51(PE3B_TX_DP5) ; also on sheet 93
P3E_CPU0_PE3_RISER2_TX_DP_6: CPU1.T50(PE3B_TX_DP6) ; also on sheet 93
P3E_CPU0_PE3_RISER2_TX_DP_7: CPU1.U49(PE3B_TX_DP7) ; also on sheet 93
PD_CPU1_BIST_ENABLE: CPU2.AJ43(BIST_ENABLE) ; also on sheet 103
PD_CPU1_TXT_PLTEN: CPU2.AF52(TXT_PLTEN) ; also on sheet 103
PECI_CPU_G: CPU2.CG55(PECI) ; also on sheet 68 139
PU_CPU1_BMCINIT: CPU2.AM48(BMCINIT) ; also on sheet 103
PU_CPU1_EAR_G_N: CPU2.CE53(EAR#) ; also on sheet 179
PU_CPU1_FRMAGENT: CPU2.Y48(FRMAGENT) ; also on sheet 103
PU_CPU1_SAFE_MODE_BOOT: CPU2.BK56(SAFE_MODE_BOOT) ; also on sheet 103
PU_CPU1_SOCKET_ID_0: CPU2.CP52(SOCKET_ID0) ; also on sheet 103
PU_CPU1_SOCKET_ID_1: CPU2.CC53(SOCKET_ID1) ; also on sheet 103
PU_CPU1_TXT_AGENT: CPU2.AH52(TXT_AGENT) ; also on sheet 103
PWRGD_CPU1_EF_DRAM_G: CPU2.CH16(DRAM_PWR_OK_C1) ; also on sheet 97
PWRGD_CPU1_G: CPU2.BJ53(PWRGOOD) ; also on sheet 97
PWRGD_CPU1_GH_DRAM_G: CPU2.W29(DRAM_PWR_OK_C23) ; also on sheet 97
RST_CPU1_G_N: CPU2.CR43(RESET#) ; also on sheet 97
SMB_DDR_EF_SCL_G: CPU2.CK42(DDR_SCL_C1) ; also on sheet 160
SMB_DDR_EF_SDA_G: CPU2.CM42(DDR_SDA_C1) ; also on sheet 160
SMB_DDR_GH_SCL_G: CPU2.V40(DDR_SCL_C23) ; also on sheet 160
SMB_DDR_GH_SDA_G: CPU2.Y40(DDR_SDA_C23) ; also on sheet 160
SRP_CPU_PWR_DEBUG_N: CPU2.AC41(PWR_DEBUG#) ; also on sheet 47 138
SVID_ALERT_CPU1_N: R14.2 ; also on sheet 16 21 35
SVID_ALERT_CPU1_R1_G: CPU2.AN43(SVIDALERT#) R14.1
SVID_CLK_CPU1: R279.2 ; also on sheet 16 21 35
SVID_CLK_CPU1_R: CPU2.AU43(SVIDCLK) R279.1
SVID_DIO_CPU1: R37.2 ; also on sheet 16 21 35
SVID_DIO_CPU1_R: CPU2.AR43(SVIDDATA) R37.1
TP_CPU1_PE_HP_SCL: CPU2.B46(PE_HP_SCL) TP89.1
TP_CPU1_PE_HP_SDA: CPU2.D46(PE_HP_SDA) TP90.1
TP_CPU1_RSVD_1: CPU2.DC3(RSVD#DC3) TP167.1
TP_CPU1_RSVD_2: CPU2.CY56(RSVD#CY56) TP165.1
TP_CPU1_RSVD_3: CPU2.R53(RSVD#R53) TP163.1
TP_CPU1_RSVD_4: CPU2.U53(RSVD#U53) TP161.1
TP_CPU1_RSVD_5: CPU2.CT50(RSVD#CT50) TP159.1
TP_CPU1_RSVD_6: CPU2.DA11(RSVD#DA11) TP157.1
TP_CPU1_RSVD_7: CPU2.BL47(RSVD#BL47) TP155.1
TP_CPU1_RSVD_8: CPU2.CA53(RSVD#CA53) TP153.1
TP_CPU1_RSVD_11: CPU2.AE45(RSVD#AE45) TP147.1
TP_CPU1_RSVD_12: CPU2.AA41(RSVD#AA41) TP145.1
TP_CPU1_RSVD_13: CPU2.Y54(RSVD#Y54) TP143.1
TP_CPU1_RSVD_14: CPU2.W41(RSVD#W41) TP166.1
TP_CPU1_RSVD_15: CPU2.V42(RSVD#V42) TP164.1
TP_CPU1_RSVD_16: CPU2.R43(RSVD#R43) TP162.1
TP_CPU1_RSVD_17: CPU2.P42(RSVD#P42) TP160.1
TP_CPU1_RSVD_18: CPU2.J41(RSVD#J41) TP158.1
TP_CPU1_RSVD_19: CPU2.H56(RSVD#H56) TP156.1
TP_CPU1_RSVD_20: CPU2.G43(RSVD#G43) TP154.1
TP_CPU1_RSVD_21: CPU2.F46(RSVD#F46) TP152.1
TP_CPU1_RSVD_22: CPU2.E53(RSVD#E53) TP150.1
TP_CPU1_RSVD_24: CPU2.C41(RSVD#C41) TP146.1
TP_CPU1_RSVD_25: CPU2.BH48(RSVD#BH48) TP144.1
TP_CPU1_RSVD_26: CPU2.AM44(RSVD#AM44) TP142.1
TP_CPU1_RSVD_27: CPU2.CF40(RSVD#CF40) TP85.1
TP_CPU1_RSVD_28: CPU2.CP40(RSVD#CP40) TP84.1
TP_CPU1_RSVD_29: CPU2.R41(RSVD#R41) TP88.1
TP_CPU1_RSVD_30: CPU2.M40(RSVD#M40) TP87.1
TP_CPU1_RSVD_33: CPU2.N41(RSVD#N41) TP127.1
TP_CPU1_RSVD_34: CPU2.CU51(RSVD#CU51) TP125.1
TP_CPU1_RSVD_35: CPU2.CW51(RSVD#CW51) TP123.1
TP_CPU1_RSVD_36: CPU2.B54(RSVD#B54) TP121.1
TP_CPU1_RSVD_37: CPU2.DB56(RSVD#DB56) TP139.1
TP_CPU1_RSVD_38: CPU2.A53(RSVD#A53) TP137.1
TP_CPU1_RSVD_39: CPU2.F58(RSVD#F58) TP135.1
TP_CPU1_RSVD_40: CPU2.E57(RSVD#E57) TP133.1
TP_CPU1_RSVD_44: CPU2.AY46(RSVD#AY46) TP94.1
TP_CPU1_RSVD_45: CPU2.AV46(RSVD#AV46) TP93.1
TP_CPU1_RSVD_46: CPU2.CR51(RSVD#CR51) TP92.1
TP_CPU1_RSVD_48: CPU2.BT44(RSVD#BT44) TP140.1
TP_CPU1_RSVD_49: CPU2.CA43(RSVD#CA43) TP138.1
TP_CPU1_RSVD_50: CPU2.BV44(RSVD#BV44) TP136.1
TP_CPU1_RSVD_51: CPU2.BY44(RSVD#BY44) TP134.1
TP_CPU1_RSVD_52: CPU2.BK44(RSVD#BK44) TP132.1
TP_CPU1_RSVD_53: CPU2.BN45(RSVD#BN45) TP130.1
TP_CPU1_RSVD_54: CPU2.BM44(RSVD#BM44) TP129.1
TP_CPU1_RSVD_55: CPU2.BR45(RSVD#BR45) TP128.1
TP_CPU1_RSVD_56: CPU2.BL43(RSVD#BL43) TP126.1
TP_CPU1_RSVD_57: CPU2.BP44(RSVD#BP44) TP124.1
TP_CPU1_RSVD_58: CPU2.BU43(RSVD#BU43) TP122.1
TP_CPU1_RSVD_59: CPU2.BR43(RSVD#BR43) TP120.1
TP_CPU1_RSVD_60: CPU2.BD44(RSVD#BD44) TP119.1
TP_CPU1_RSVD_61: CPU2.BF44(RSVD#BF44) TP118.1
TP_CPU1_RSVD_62: CPU2.BH46(RSVD#BH46) TP117.1
TP_CPU1_RSVD_63: CPU2.BG43(RSVD#BG43) TP115.1
TP_CPU1_RSVD_64: CPU2.BE43(RSVD#BE43) TP113.1
TP_CPU1_RSVD_65: CPU2.BJ45(RSVD#BJ45) TP112.1
TP_CPU1_RSVD_66: CPU2.BH44(RSVD#BH44) TP111.1
TP_CPU1_RSVD_67: CPU2.BJ43(RSVD#BJ43) TP100.1
TP_CPU1_RSVD_68: CPU2.DE53(RSVD#DE53) TP110.1
TP_CPU1_RSVD_70: CPU2.F56(RSVD#F56) TP108.1
TP_CPU1_RSVD_71: CPU2.D56(RSVD#D56) TP99.1
TP_CPU1_RSVD_72: CPU2.K58(RSVD#K58) TP98.1
TP_CPU1_RSVD_73: CPU2.H58(RSVD#H58) TP104.1
TP_CPU1_RSVD_76: CPU2.DE55(RSVD#DE55) TP109.1
TP_CPU1_RSVD_77: CPU2.DD54(RSVD#DD54) TP107.1
TP_CPU1_RSVD_78: CPU2.CY58(RSVD#CY58) TP106.1
TP_CPU1_RSVD_79: CPU2.DA57(RSVD#DA57) TP105.1
TP_CPU1_RSVD_80: CPU2.BP46(RSVD#BP46) TP103.1
TP_CPU1_RSVD_81: CPU2.BM46(RSVD#BM46) TP97.1
TP_CPU1_RSVD_82: CPU2.CN43(RSVD#CN43) TP114.1
TP_CPU1_RSVD_83: CPU2.CL43(RSVD#CL43) TP116.1
TP_CPU1_TEST_0: CPU2.DB2(TEST0) R410.1
TP_CPU1_TEST_1: CPU2.DB4(TEST1) R332.1
TP_CPU1_TEST_2: CPU2.D2(TEST2) R415.1
TP_CPU1_TEST_3: CPU2.C3(TEST3) R413.1
VSENSE_PVCCIN_CPU0_N: CPU1.BP2(VSS_VCCIN_SENSE) ; also on sheet 36 39
VSENSE_PVCCIN_CPU0_P: CPU1.BN1(VCCIN_SENSE) ; also on sheet 36 39
XDP_CPU1_OBSDATA_B_MBP2_G_N: CPU2.BE47(BPM_N2) ; also on sheet 47
XDP_CPU1_OBSDATA_B_MBP3_G_N: CPU2.BF46(BPM_N3) ; also on sheet 47
XDP_CPU1_OBSDATA_B_MBP4_G_N: CPU2.BE45(BPM_N4) ; also on sheet 47
XDP_CPU1_OBSDATA_B_MBP5_G_N: CPU2.BD46(BPM_N5) ; also on sheet 47
XDP_CPU1_PRDY_G_N: CPU2.CU49(PRDY#) ; also on sheet 46
XDP_CPU1_PREQ_G_N: CPU2.CW49(PREQ#) ; also on sheet 46
XDP_CPU1_TDI_G: CPU2.CF42(TDI) ; also on sheet 46
XDP_CPU1_TDO_G: CPU2.CG41(TDO) ; also on sheet 46
XDP_CPU_MBP0_G_N: CPU2.BC43(BPM_N0) R16.2 ; also on sheet 139
XDP_CPU_MBP1_G_N: CPU2.BB44(BPM_N1) R15.2 ; also on sheet 139
XDP_CPU_OBSFN_B_MBP6_G_N: CPU2.BA43(BPM_N6) ; also on sheet 47 139
XDP_CPU_OBSFN_B_MBP7_G_N: CPU2.AW43(BPM_N7) ; also on sheet 47 139
XDP_CPU_TCK_G: CPU2.CA45(TCK) ; also on sheet 46 47 139
XDP_CPU_TMS_G: CPU2.BY46(TMS) ; also on sheet 46 47 139
XDP_CPU_TRST_G_N: CPU2.CV50(TRST#) ; also on sheet 46 47 139
XDP_PRESENT_N: CPU2.F40(DEBUG_EN#) ; also on sheet 47 138

Not connected (* = marked no-connect by the designer): CPU2 AJ55(RSVD#AJ55)* AL55(RSVD#AL55)* AM54(RSVD#AM54)* AP48(RSVD#AP48)* AR55(RSVD#AR55)* AU55(RSVD#AU55)* BD48(RSVD#BD48)* BF48(RSVD#BF48)* C53(RSVD#C53)* CC15(DDR0_CKE5)* CE25(DDR0_ODT5)* CF24(DDR0_ODT4)* CK24(DDR0_CS8#)* CK26(DDR0_CS9#)* CN15(DDR0_CKE4)* CY16(DDR1_CKE4)* DA15(DDR1_CKE5)* DA25(DDR1_ODT4)* DD26(DDR1_ODT5)* DF24(DDR1_CS8#)* DF26(DDR1_CS9#)*

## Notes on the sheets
sheet 126
- CPU2 - DDR4 (CHANNEL F)
- FAB1 REV003 20150318
sheet 127
- CPU2 - DDR4 (CHANNEL E)
- FAB1 REV003 20150318
sheet 128
- CPU2 - RESERVED PINS
sheet 129
- CPU2 - MICS
- All clocks to all Intel QPI agents (processors) should
  be routed on the same physical layer and must be
  matched within 0.5 inches.
- All processors must receive
  inactive to active transitions of PWRGOOD signal within 10 ns of each other.
- FROM CLK BUFFER
- FROM CLK BUFFER
- FAB1 REV004 20150320
- PLACE NEAR CPU1
- SVID PDG P.250
- FAB1 REV024 20150429
- ¡E Resistor values tolerance must not exceed 5%.
  ¡E Trace length matching must be used between the Clock and Data lines to ensure a
  length difference of no more than 250 mils.
  ¡E Data line should be routed between Alert and Clock lines.
  ¡E Good high-speed design practices must be used, such as avoiding routing over
  voids. If split crossing can¡¦t be avoided, place a decoupling capacitor between the
  two planes, within 0.150 in. of the SVID lines at each split crossing (0.1 £gF is
  recommended).
  ¡E SVID must be ground reference. Do not route SVID bus signals under phase nodes
  or high side MOSFET nodes that generate electrical noise.
  ¡E Routing impedance of the 3 lines should ensure nominal 50 ohm impedance.
  ¡E Low inductance path for VIO termination voltage to termination resistors (10 mils
  is the minimum trace width allowed). Bypass termination voltage as close as
  possible to termination resistor with 10 £gF and 0.1 £gF capacitors to ground
  (bypass is required unless supplied from a full plane).
  ¡E Microstrip (MS) and Stripline (SL) routing is allowed. Spacing of 12 mil on MS and
  13.5 mil on SL within the Clock and Data, and 15 mil to all other nonstatic lines.
  For 10 mil of spacing on SL, do not exceed this spacing for more than 2.5 inches.
  An exception is for the breakout regions, spacing between lines can drop to mil for
  coupling lengths less than 0.5 inches.
- Remove components
sheet 130
- CPU1 - VCCIN & VDDQ
sheet 131
- CPU1 - PCIE (3A-3D)
- To Mezzanine
- To Mezzanine
- To Mid-Plane
- To Mid-Plane
